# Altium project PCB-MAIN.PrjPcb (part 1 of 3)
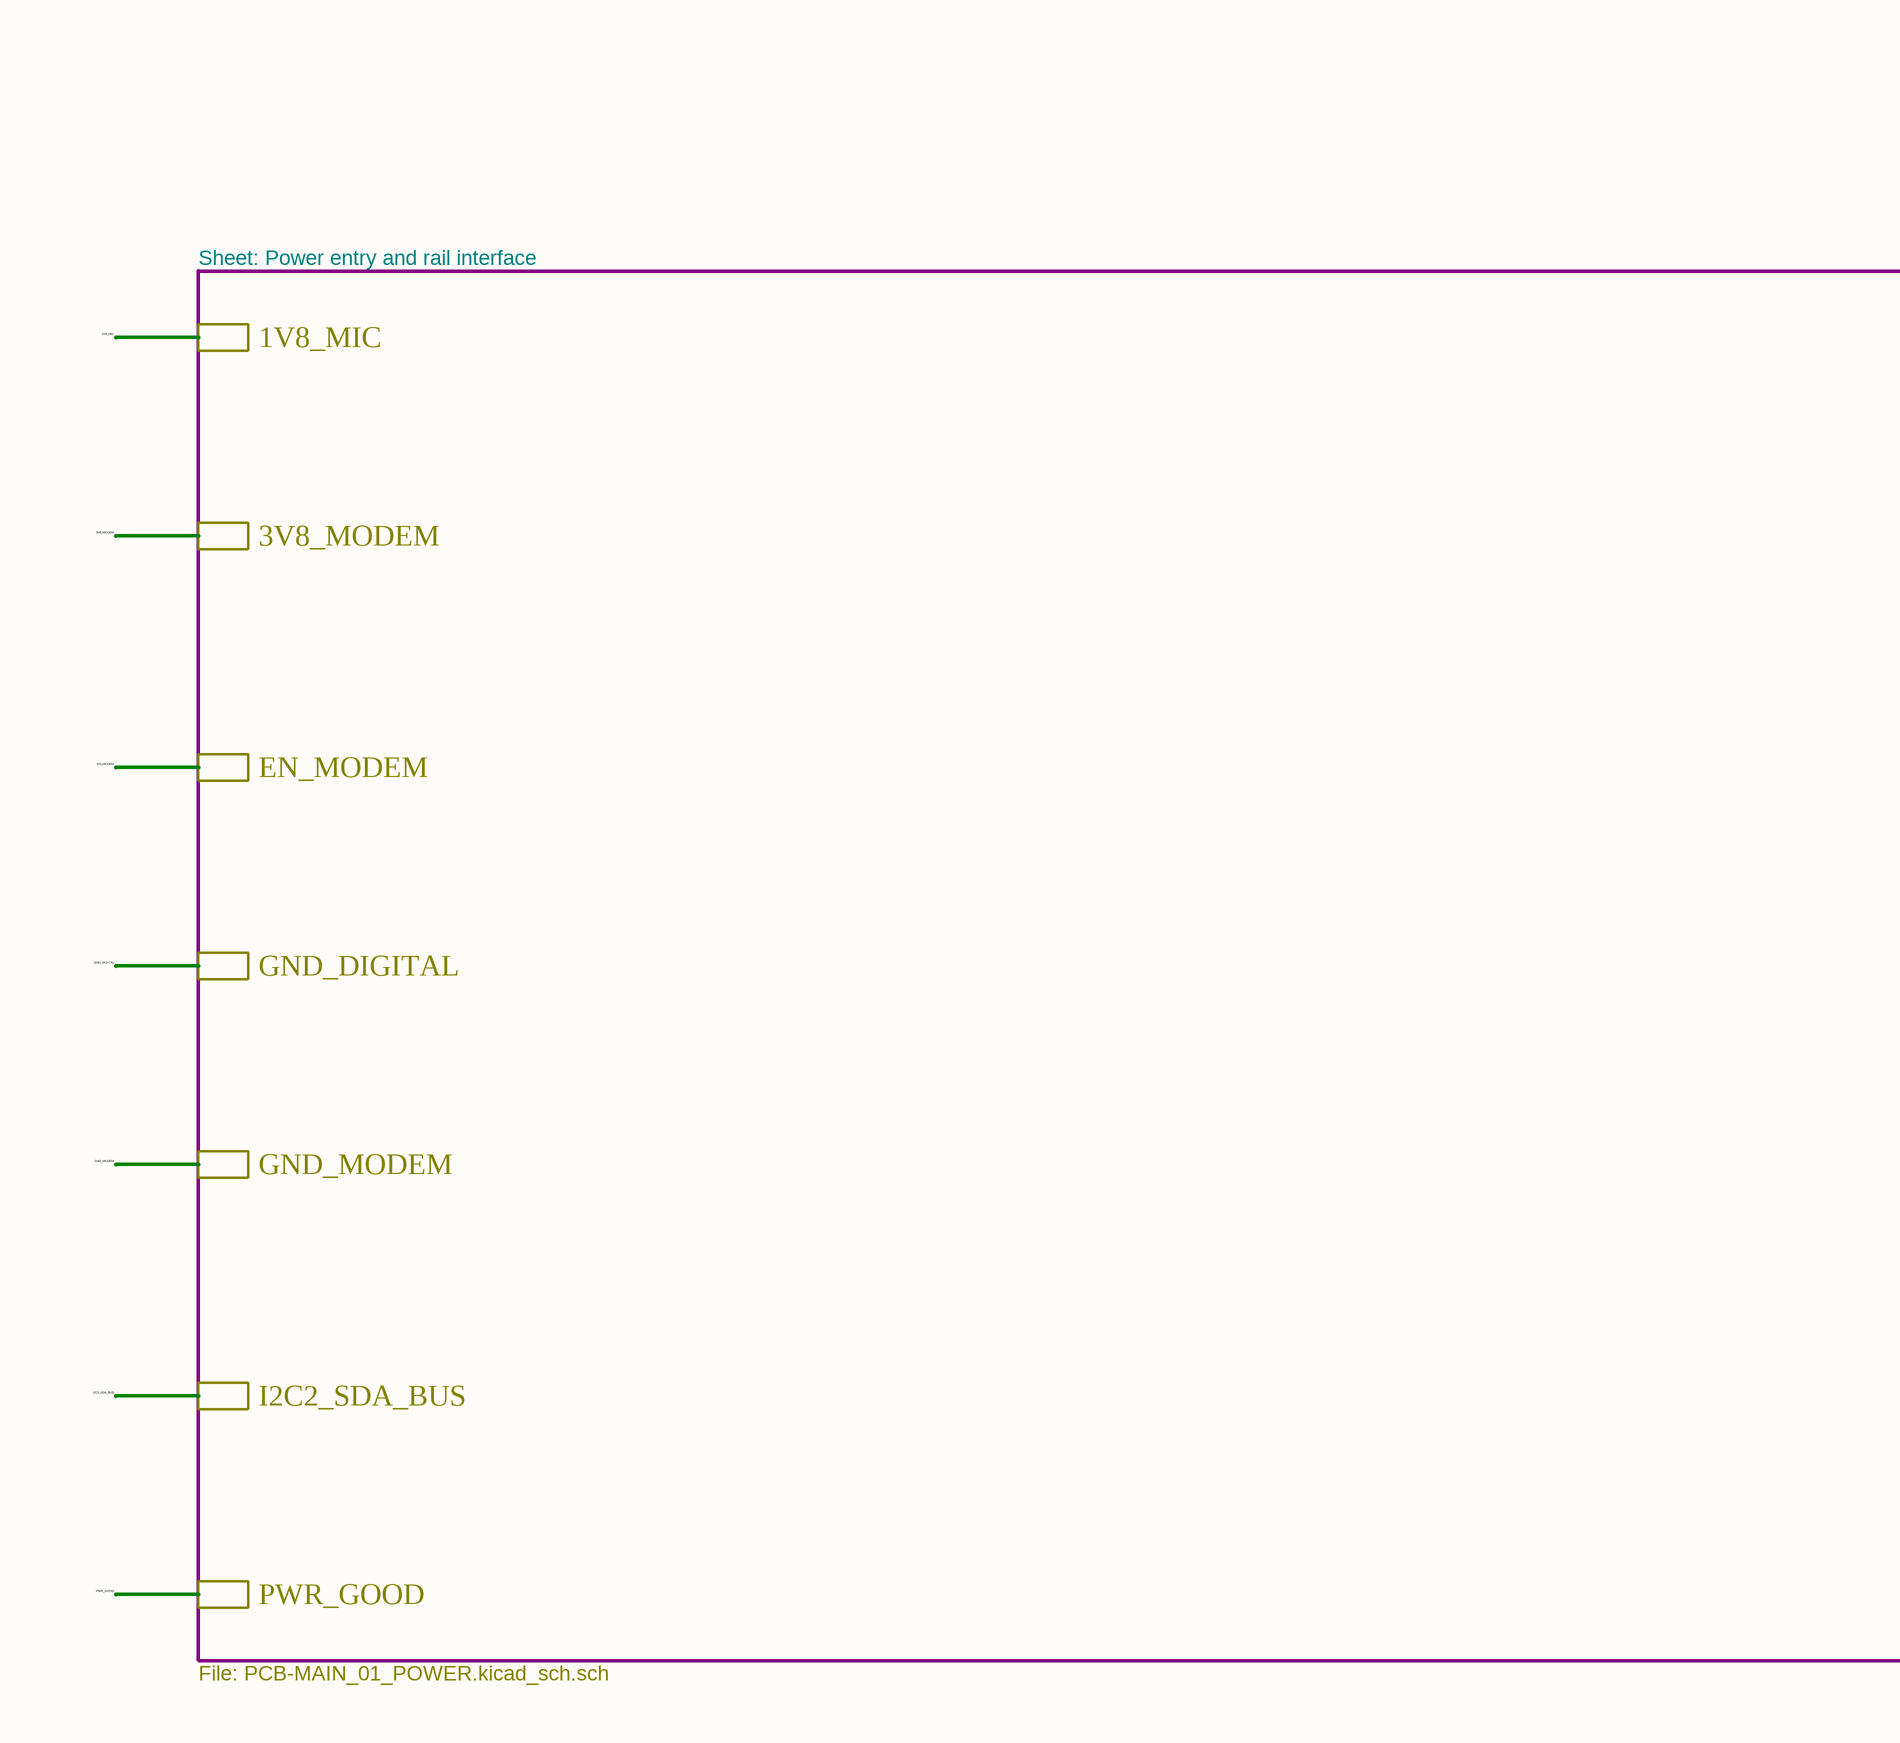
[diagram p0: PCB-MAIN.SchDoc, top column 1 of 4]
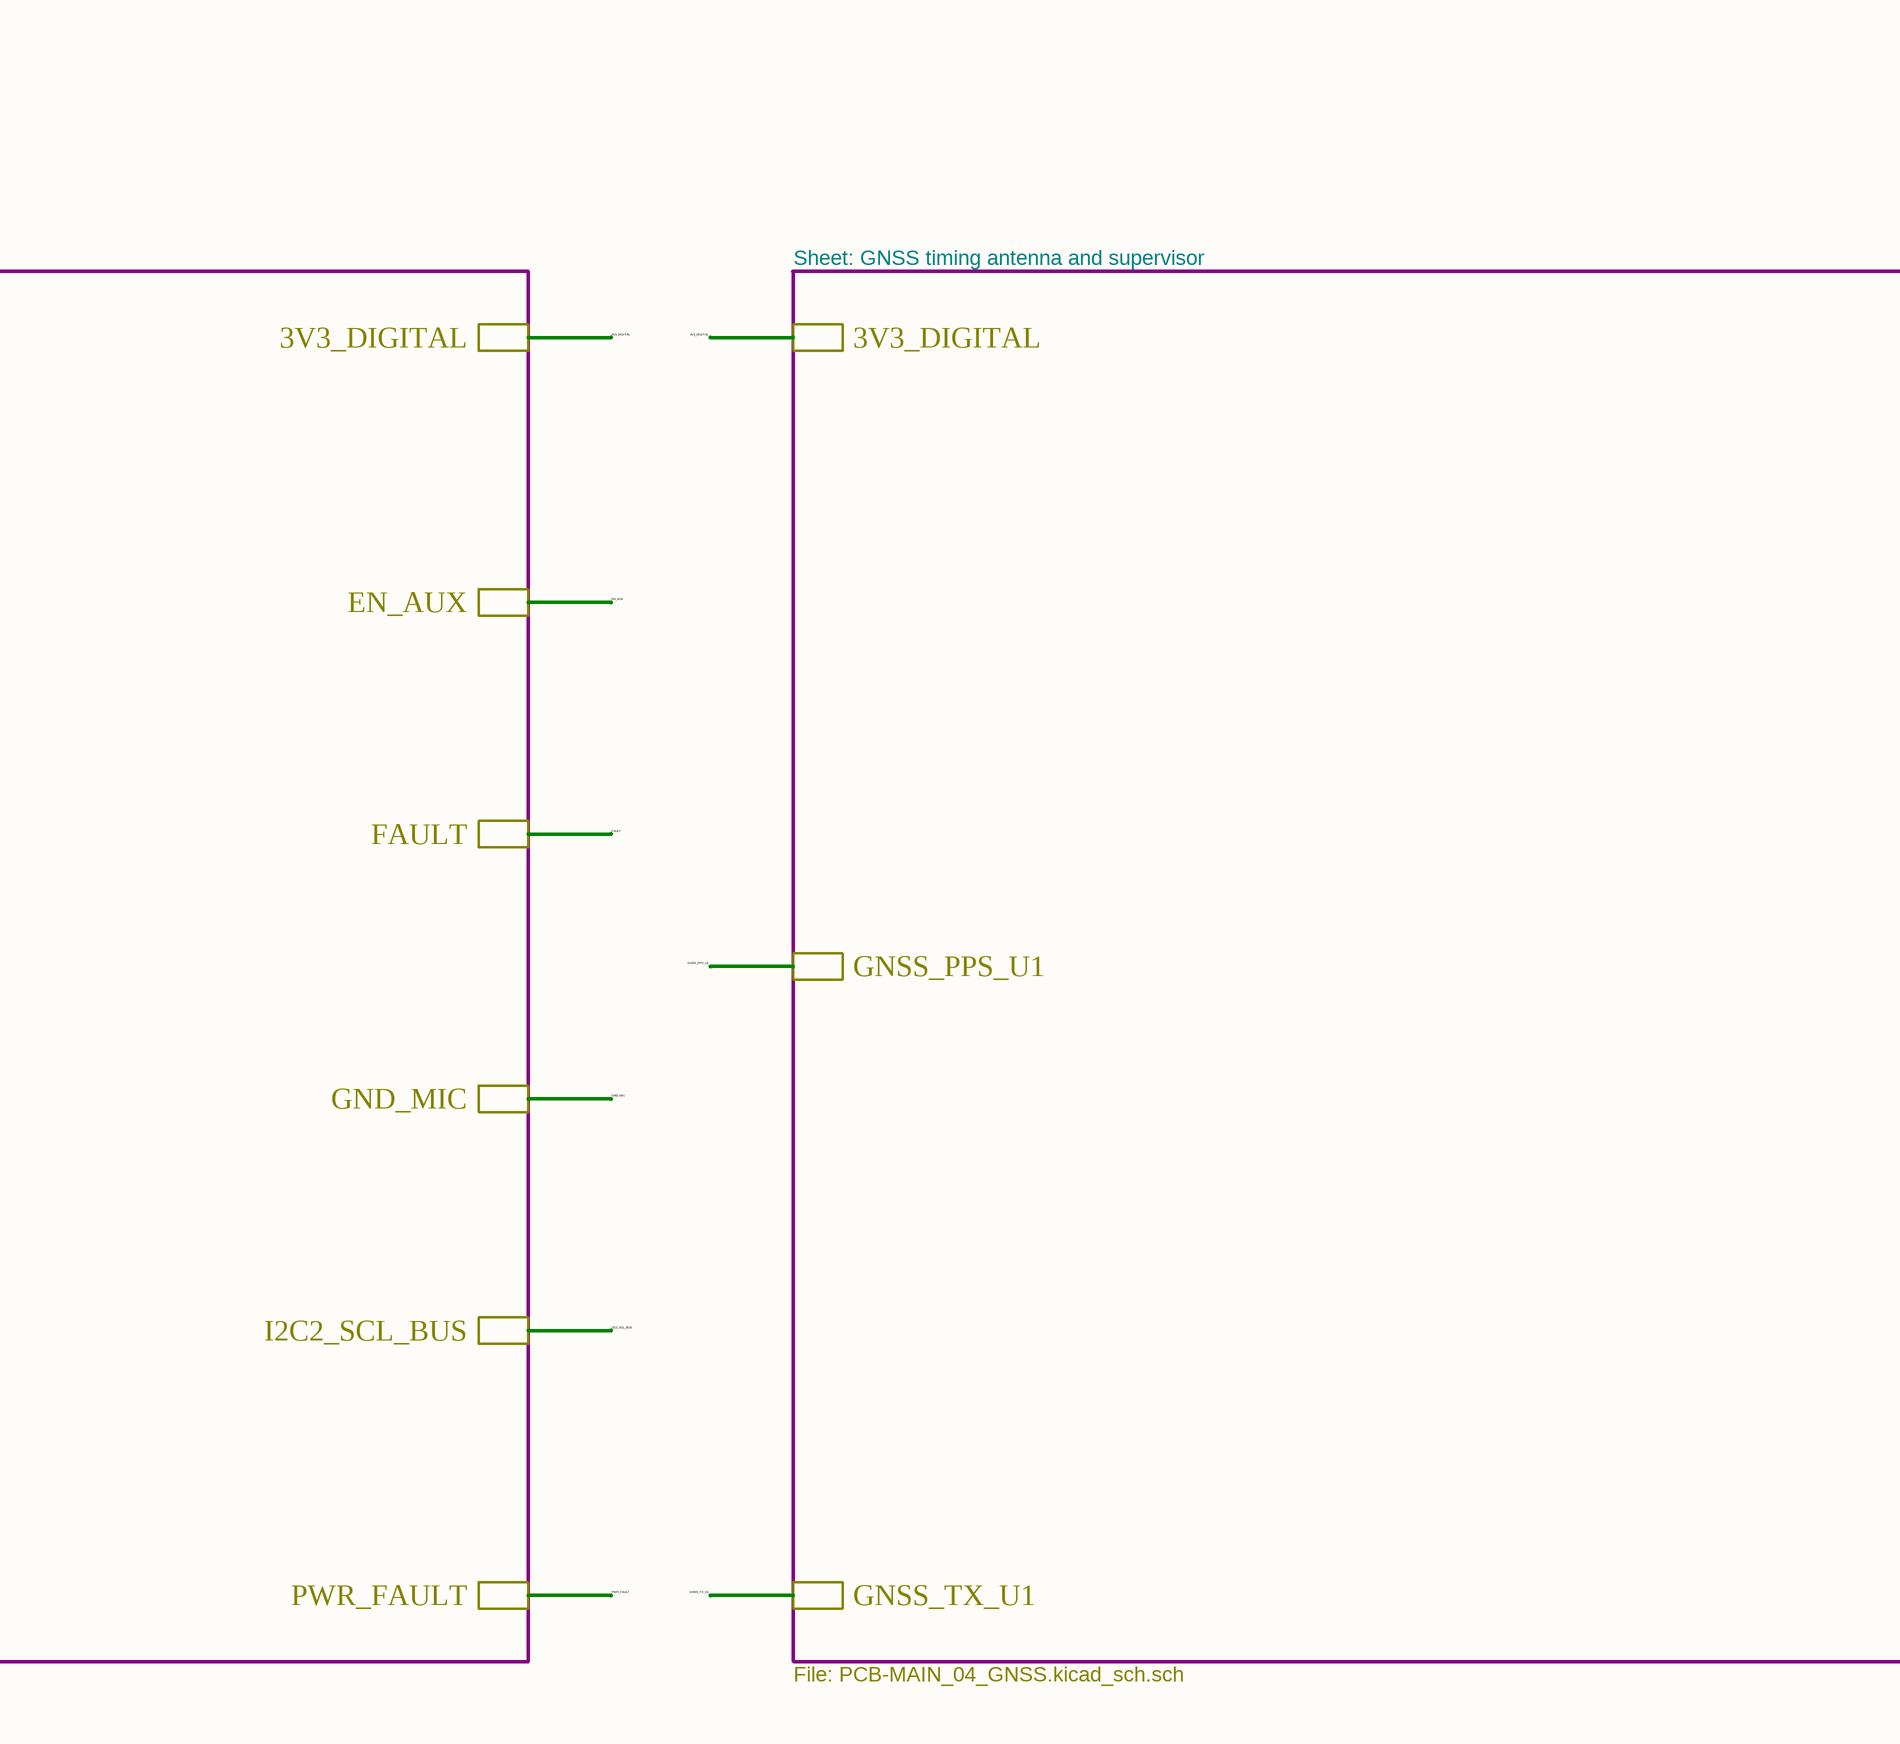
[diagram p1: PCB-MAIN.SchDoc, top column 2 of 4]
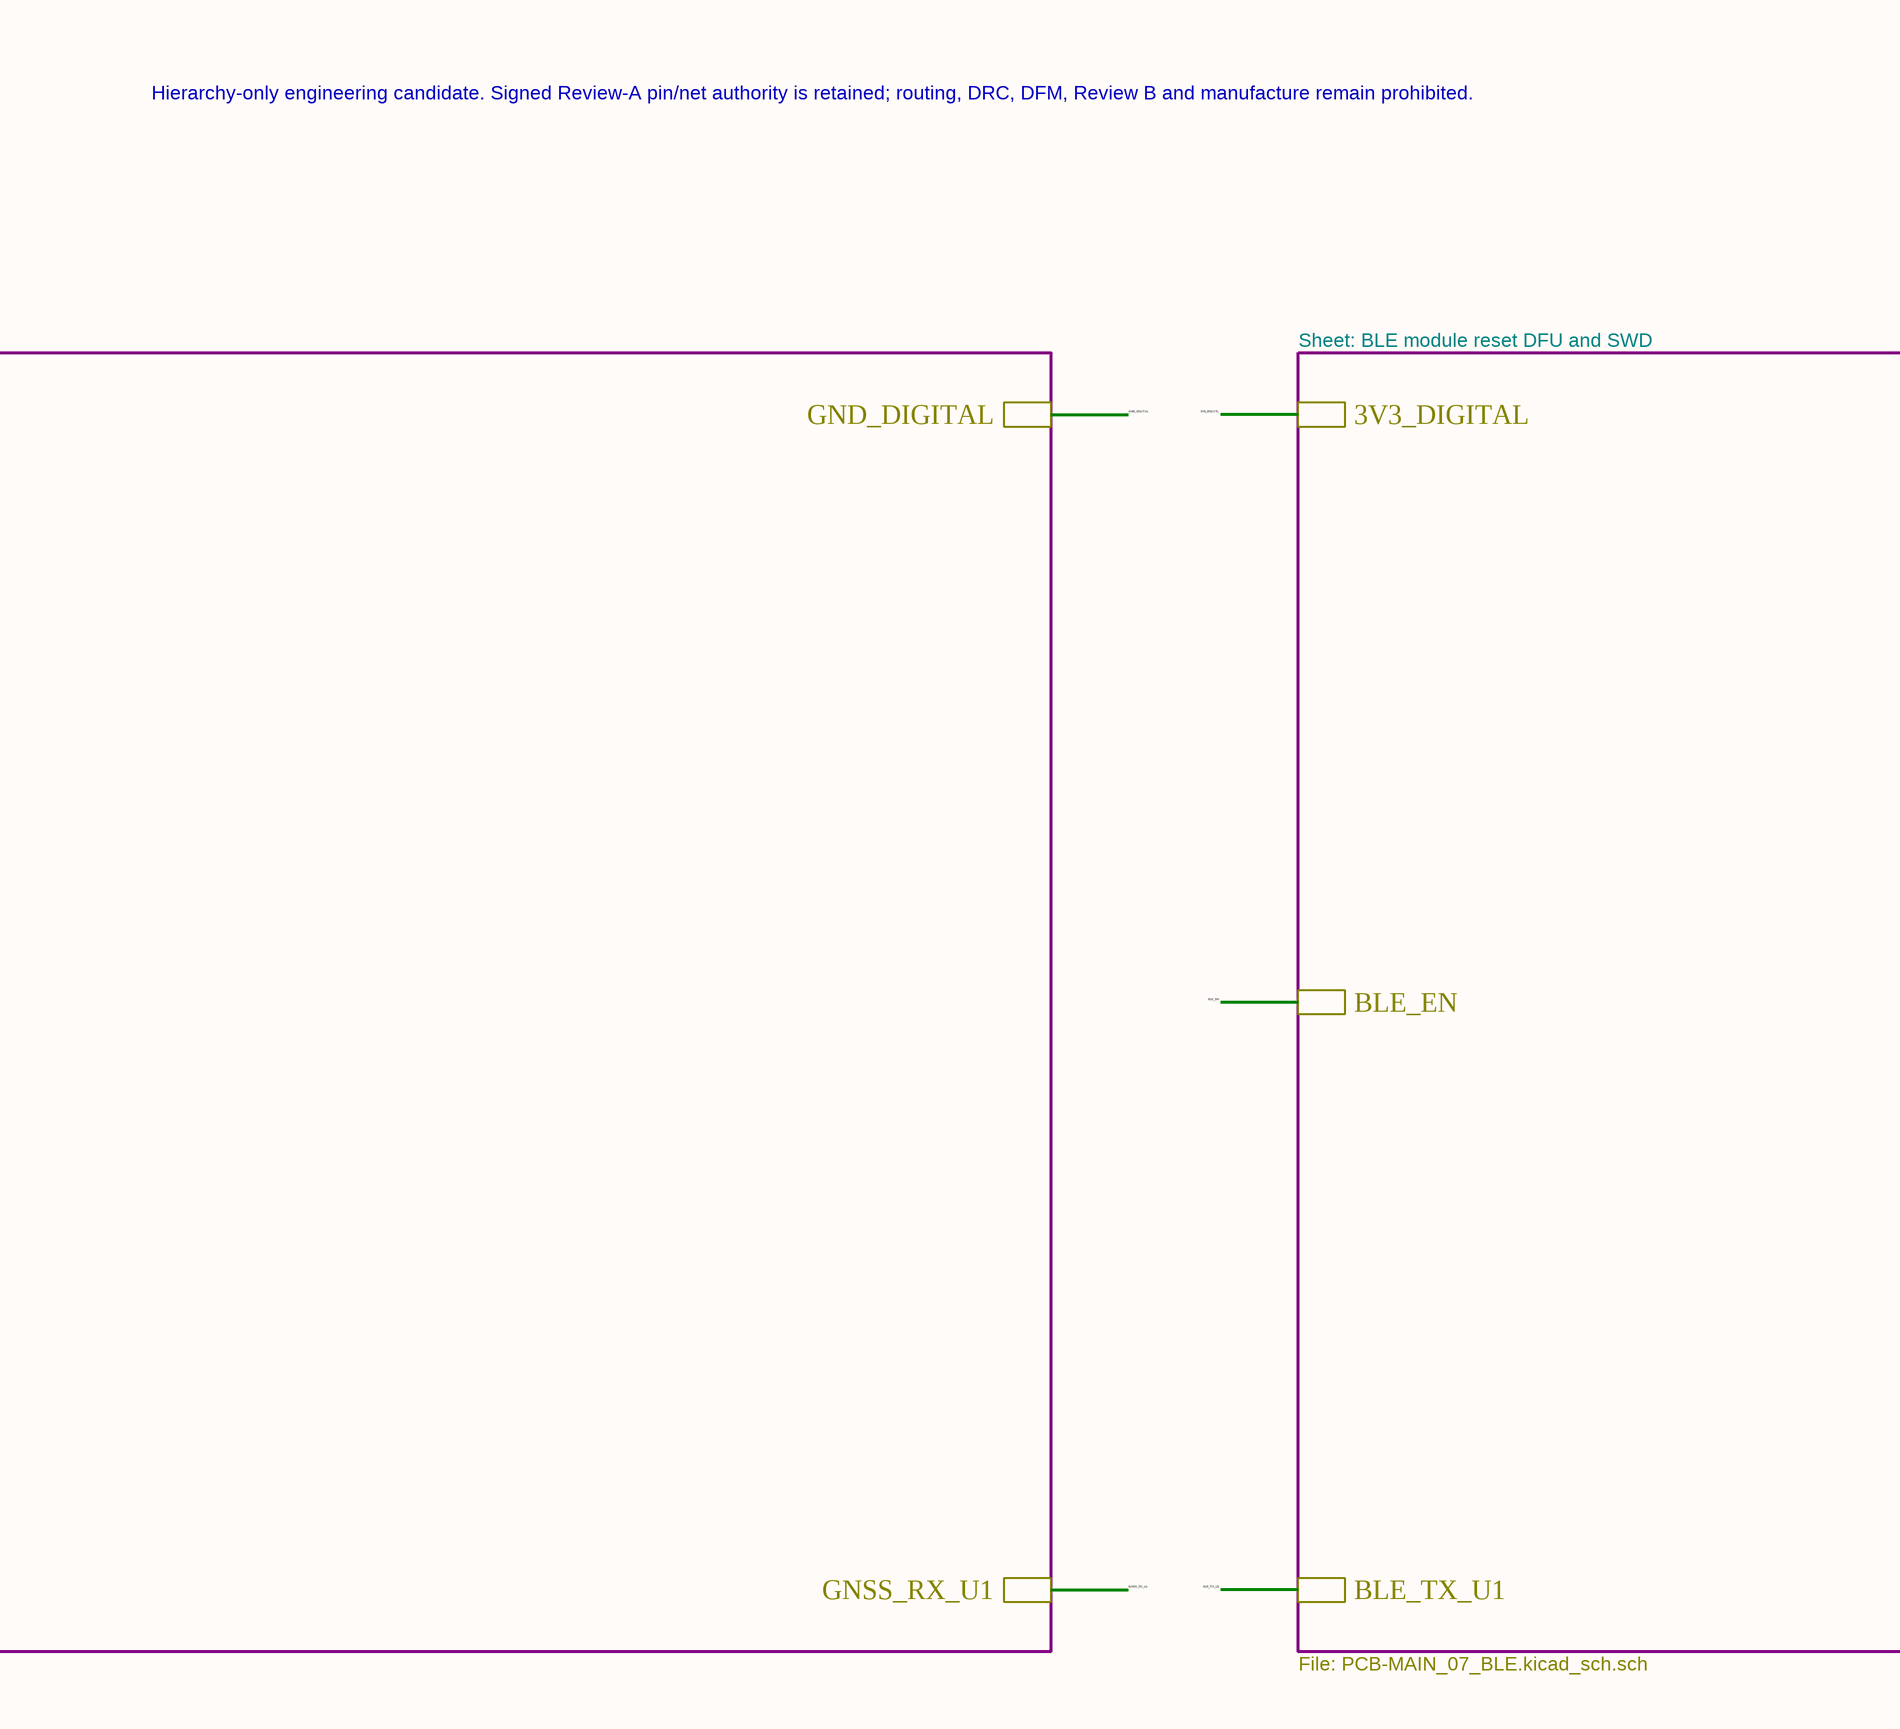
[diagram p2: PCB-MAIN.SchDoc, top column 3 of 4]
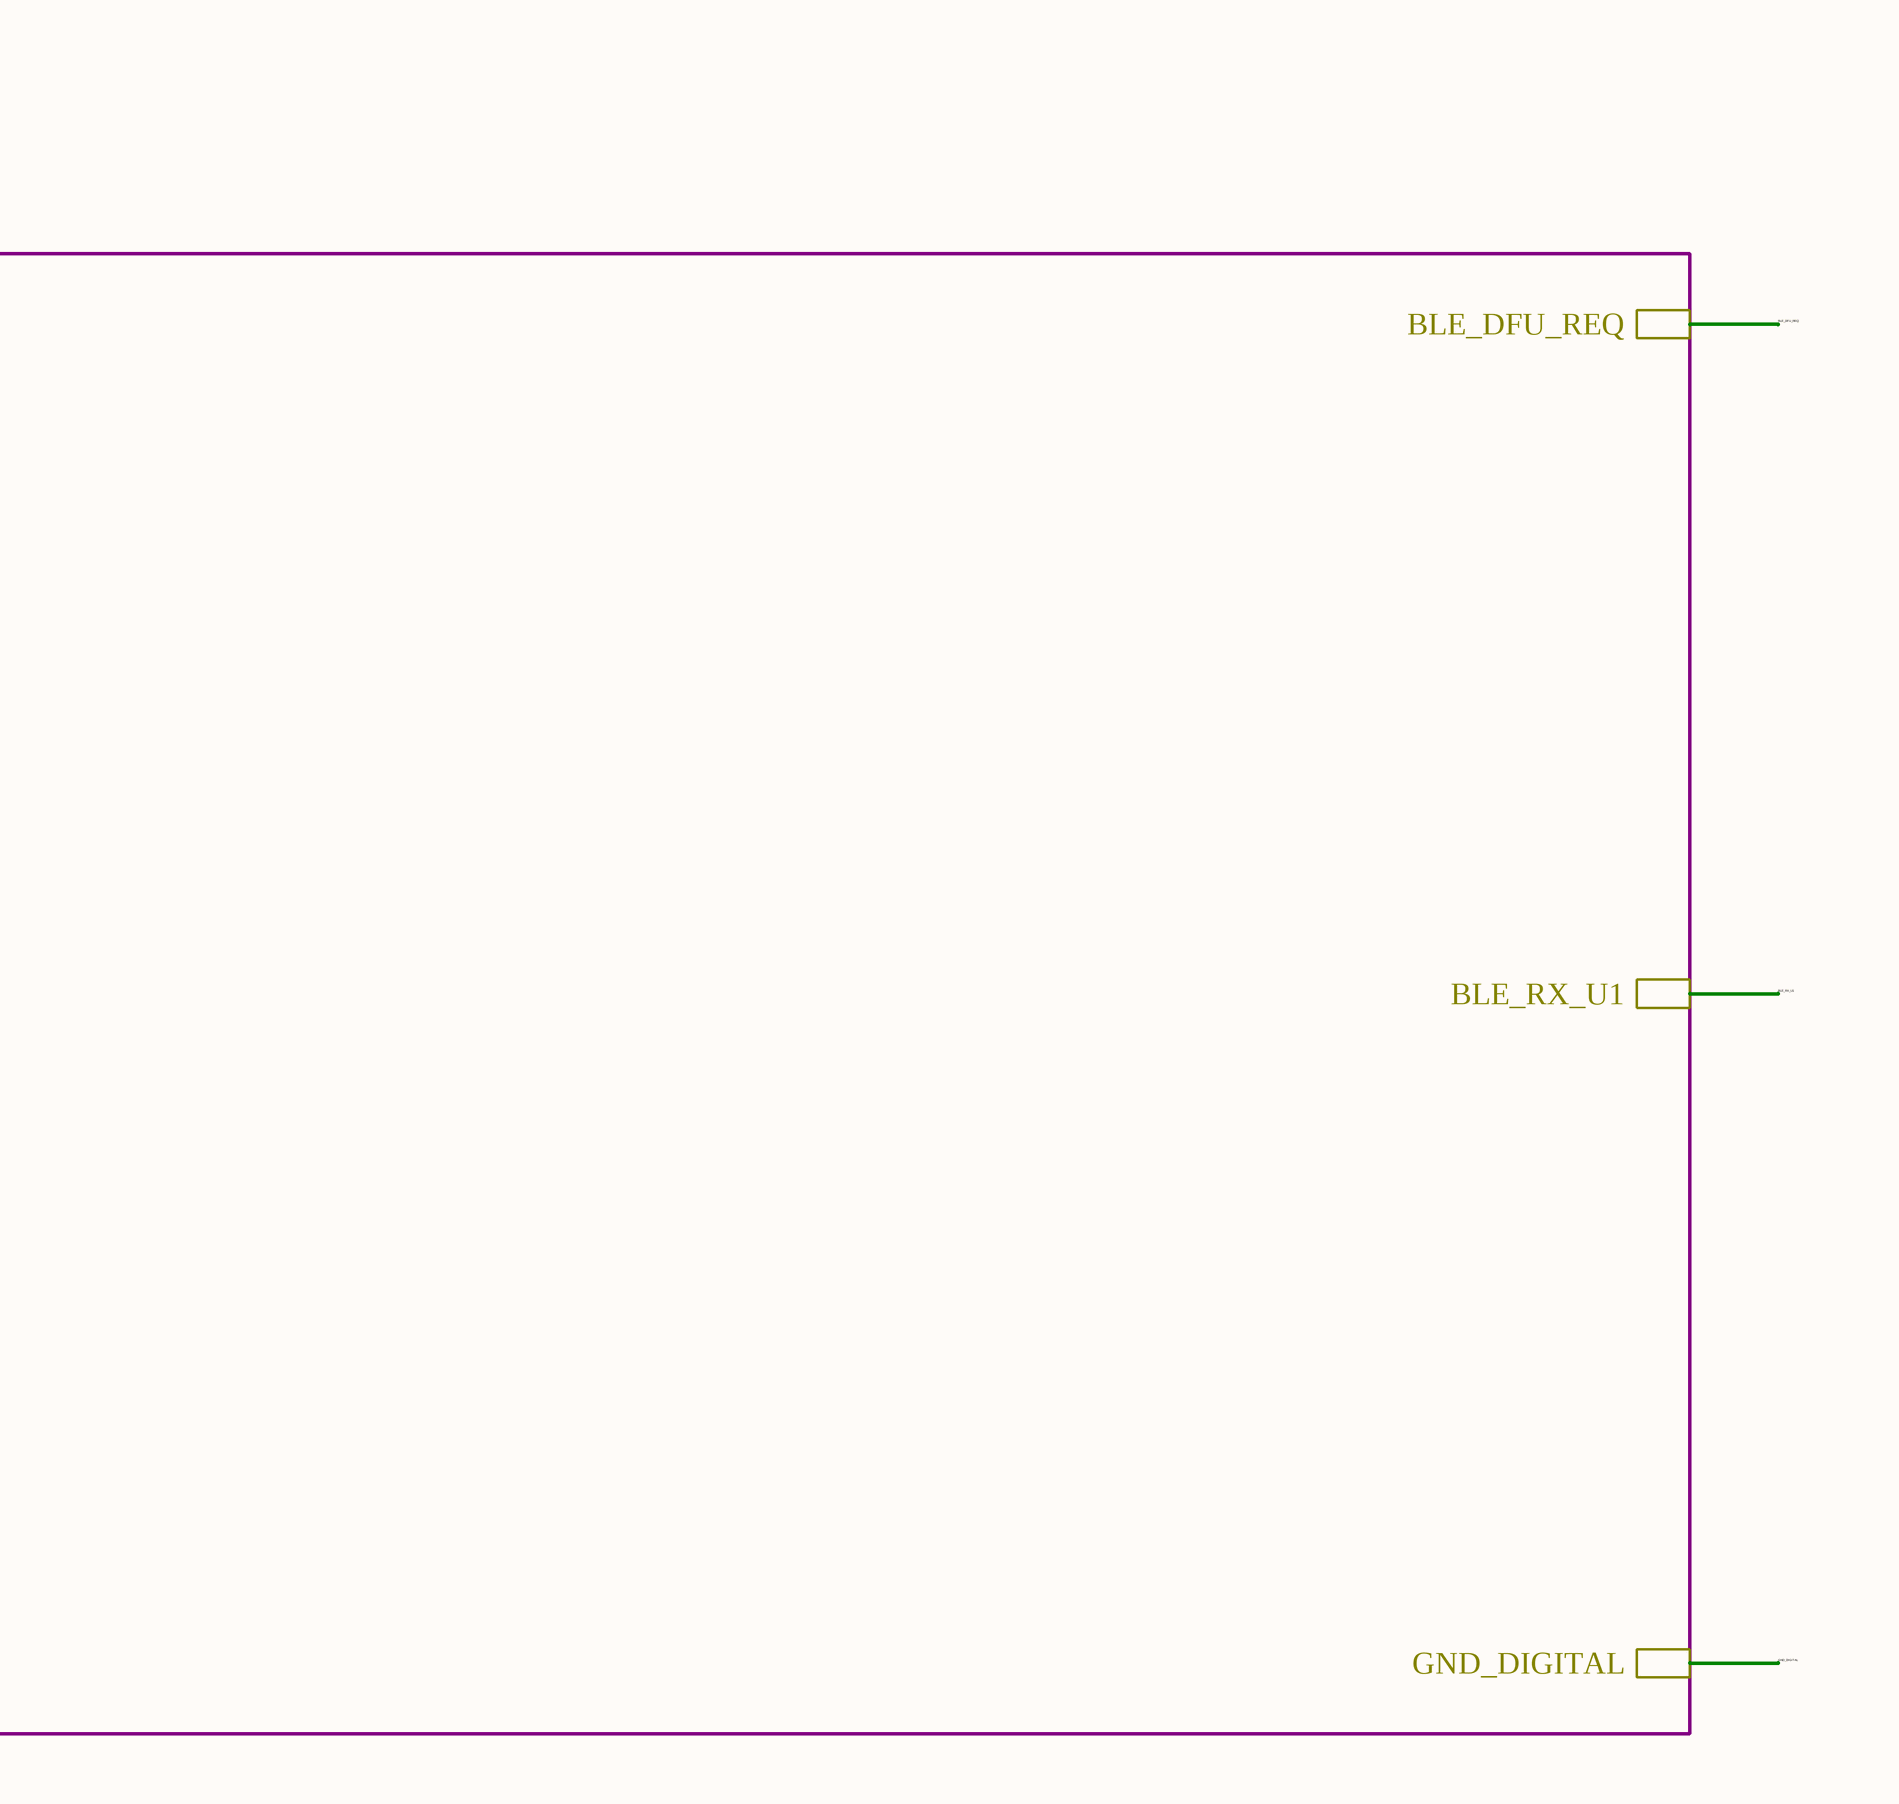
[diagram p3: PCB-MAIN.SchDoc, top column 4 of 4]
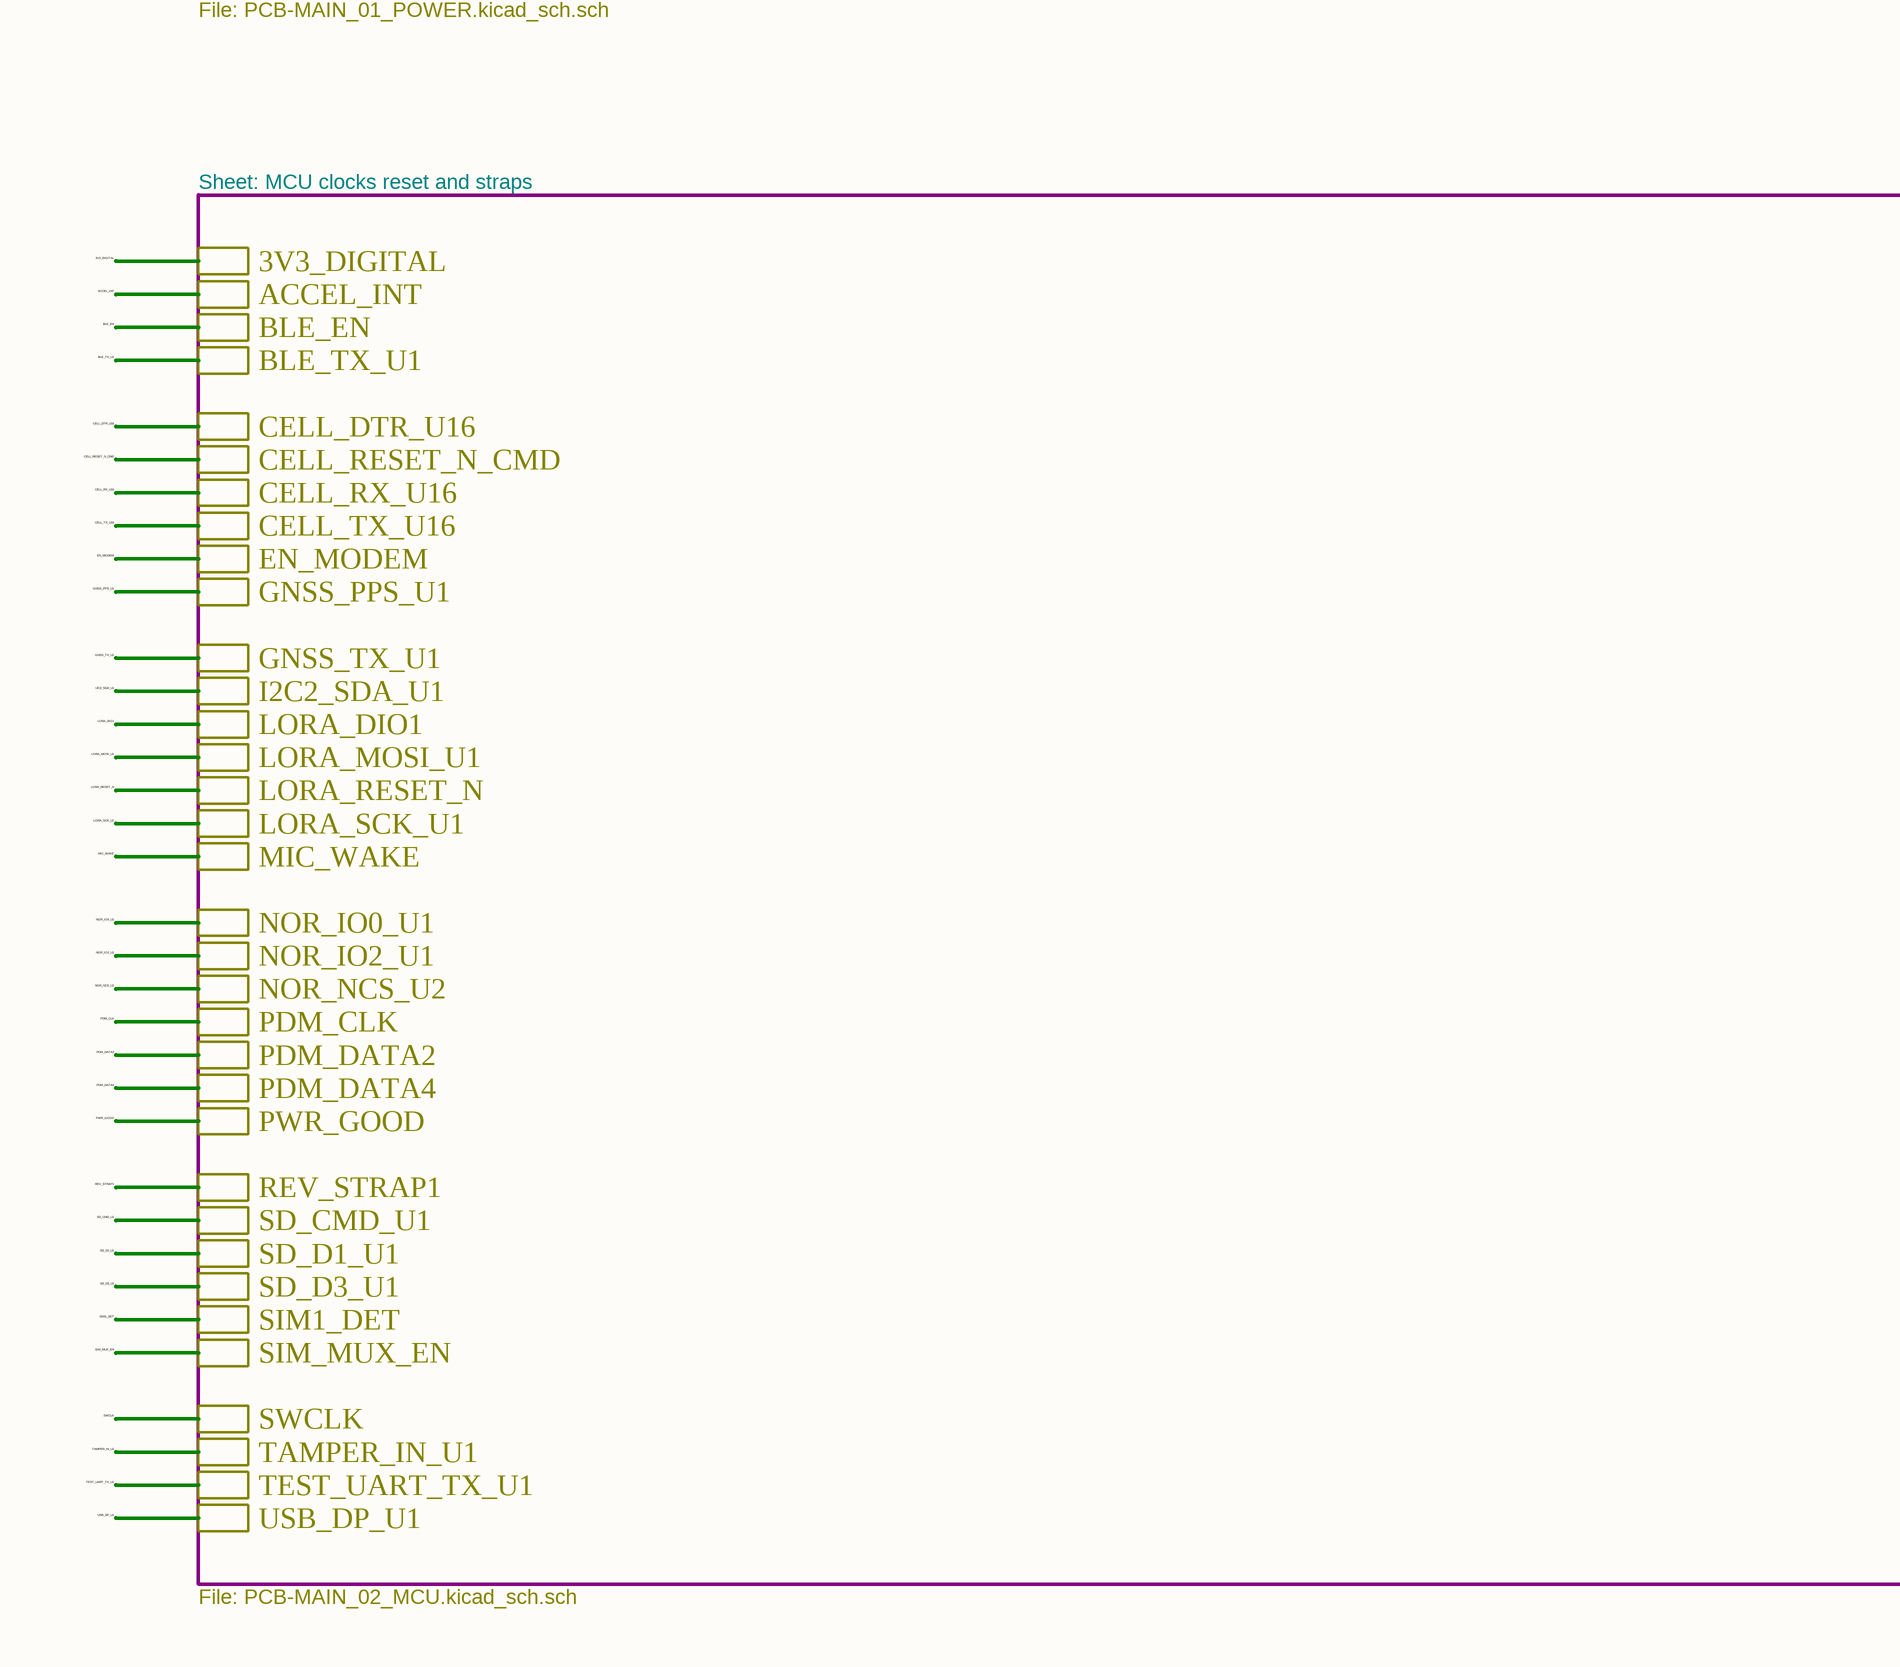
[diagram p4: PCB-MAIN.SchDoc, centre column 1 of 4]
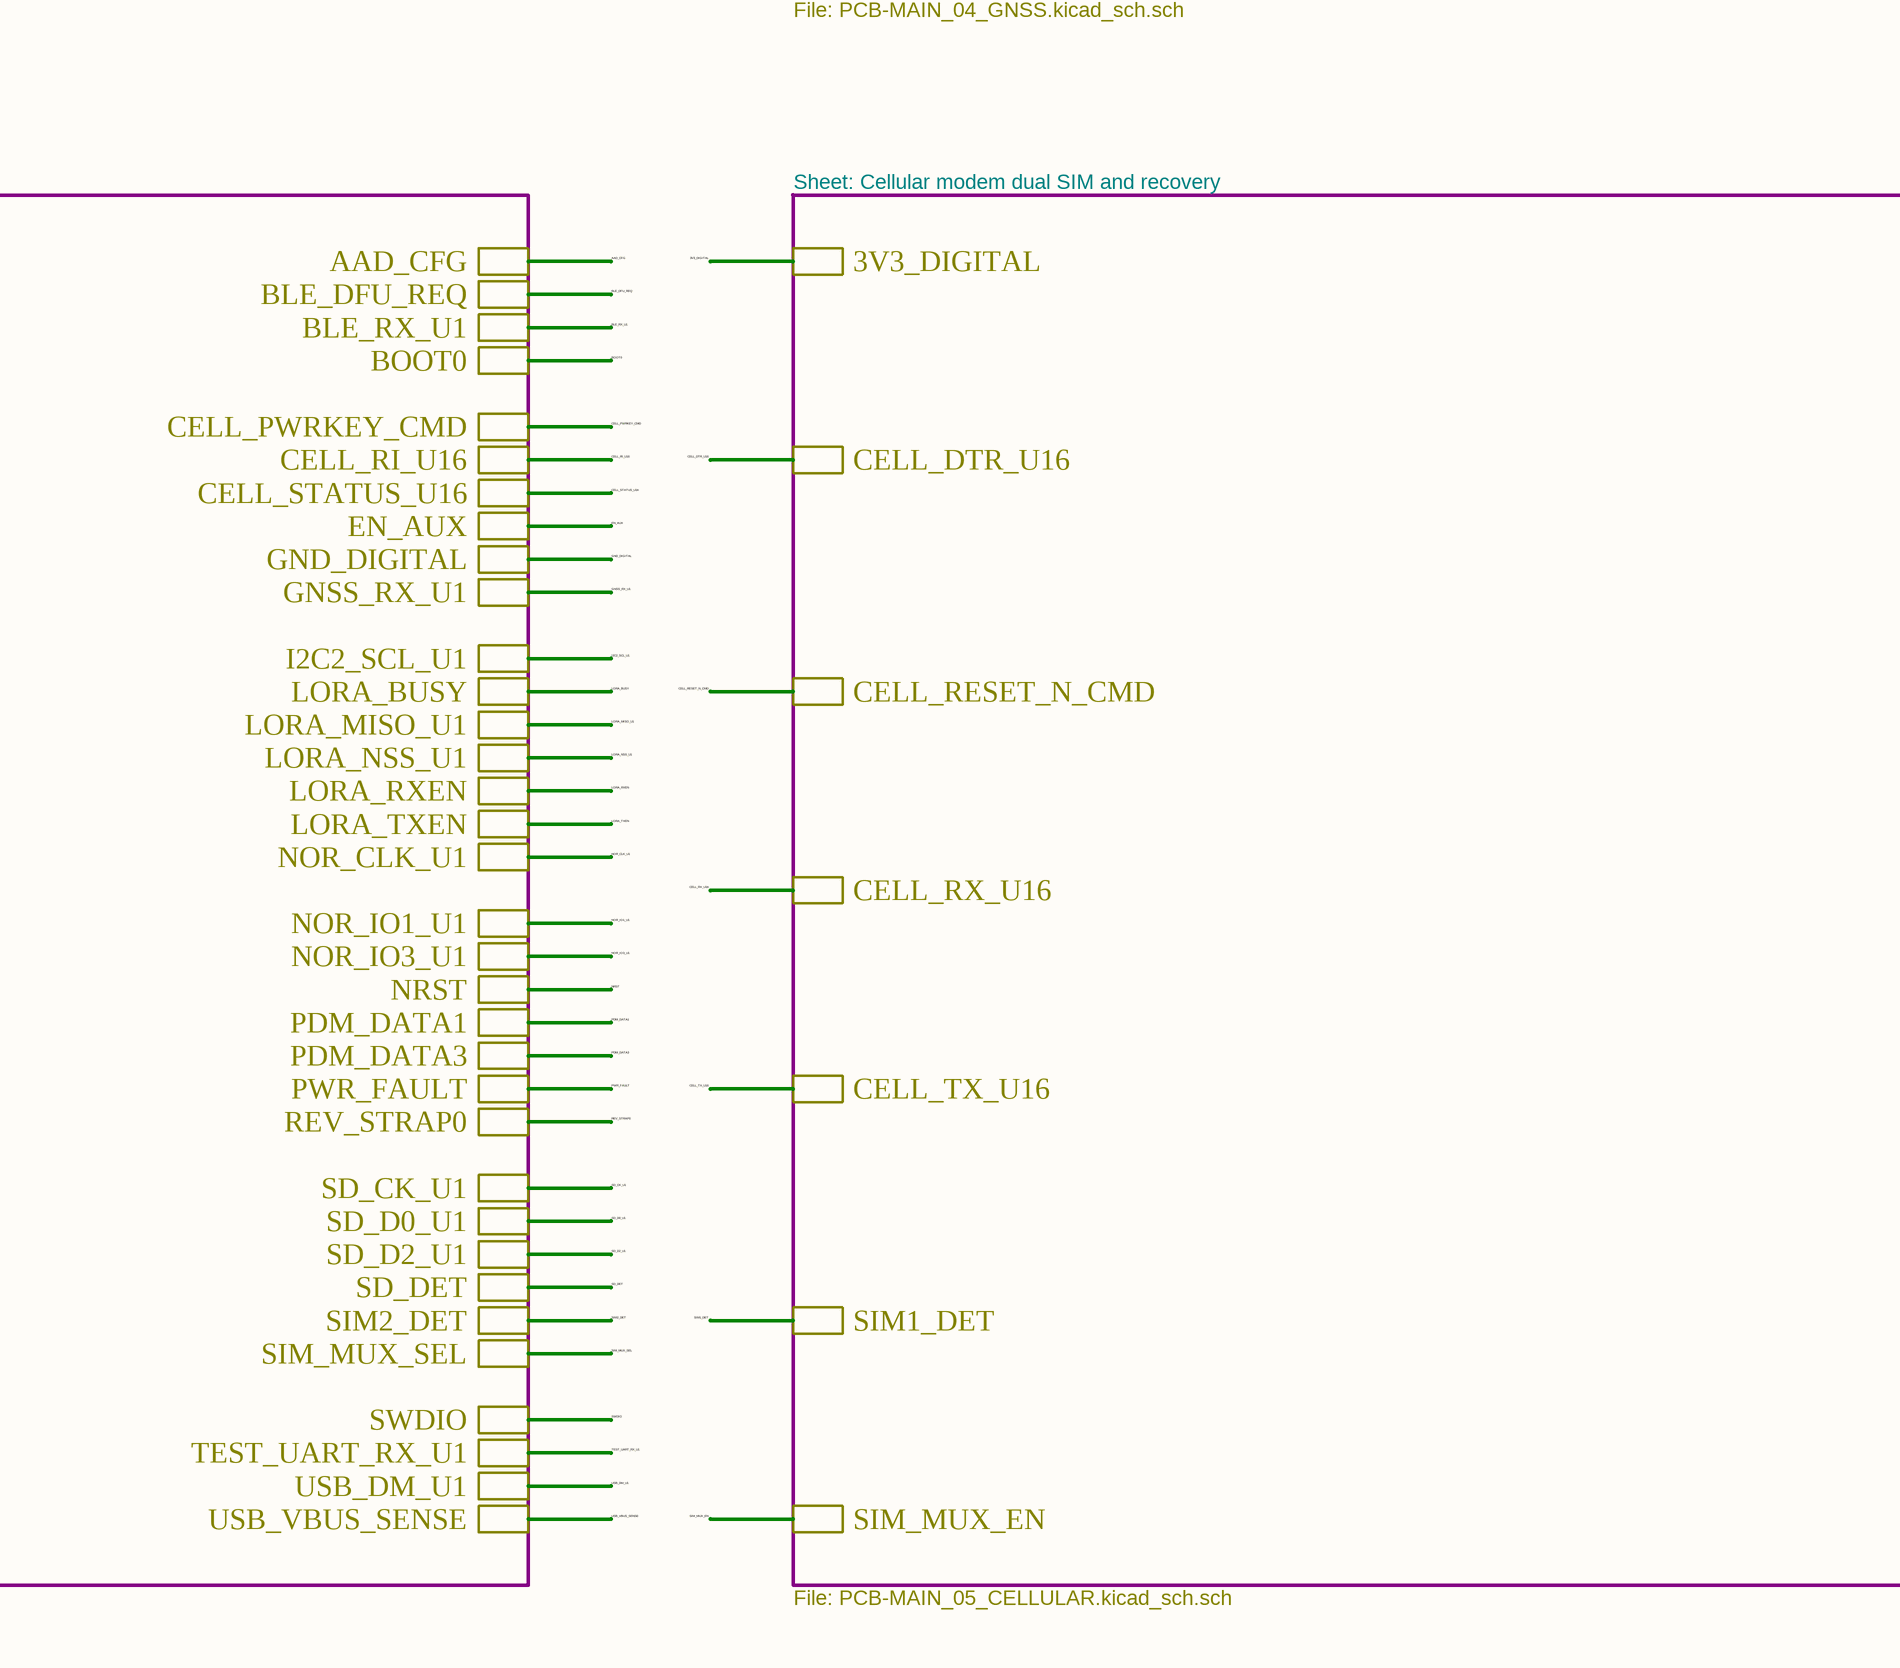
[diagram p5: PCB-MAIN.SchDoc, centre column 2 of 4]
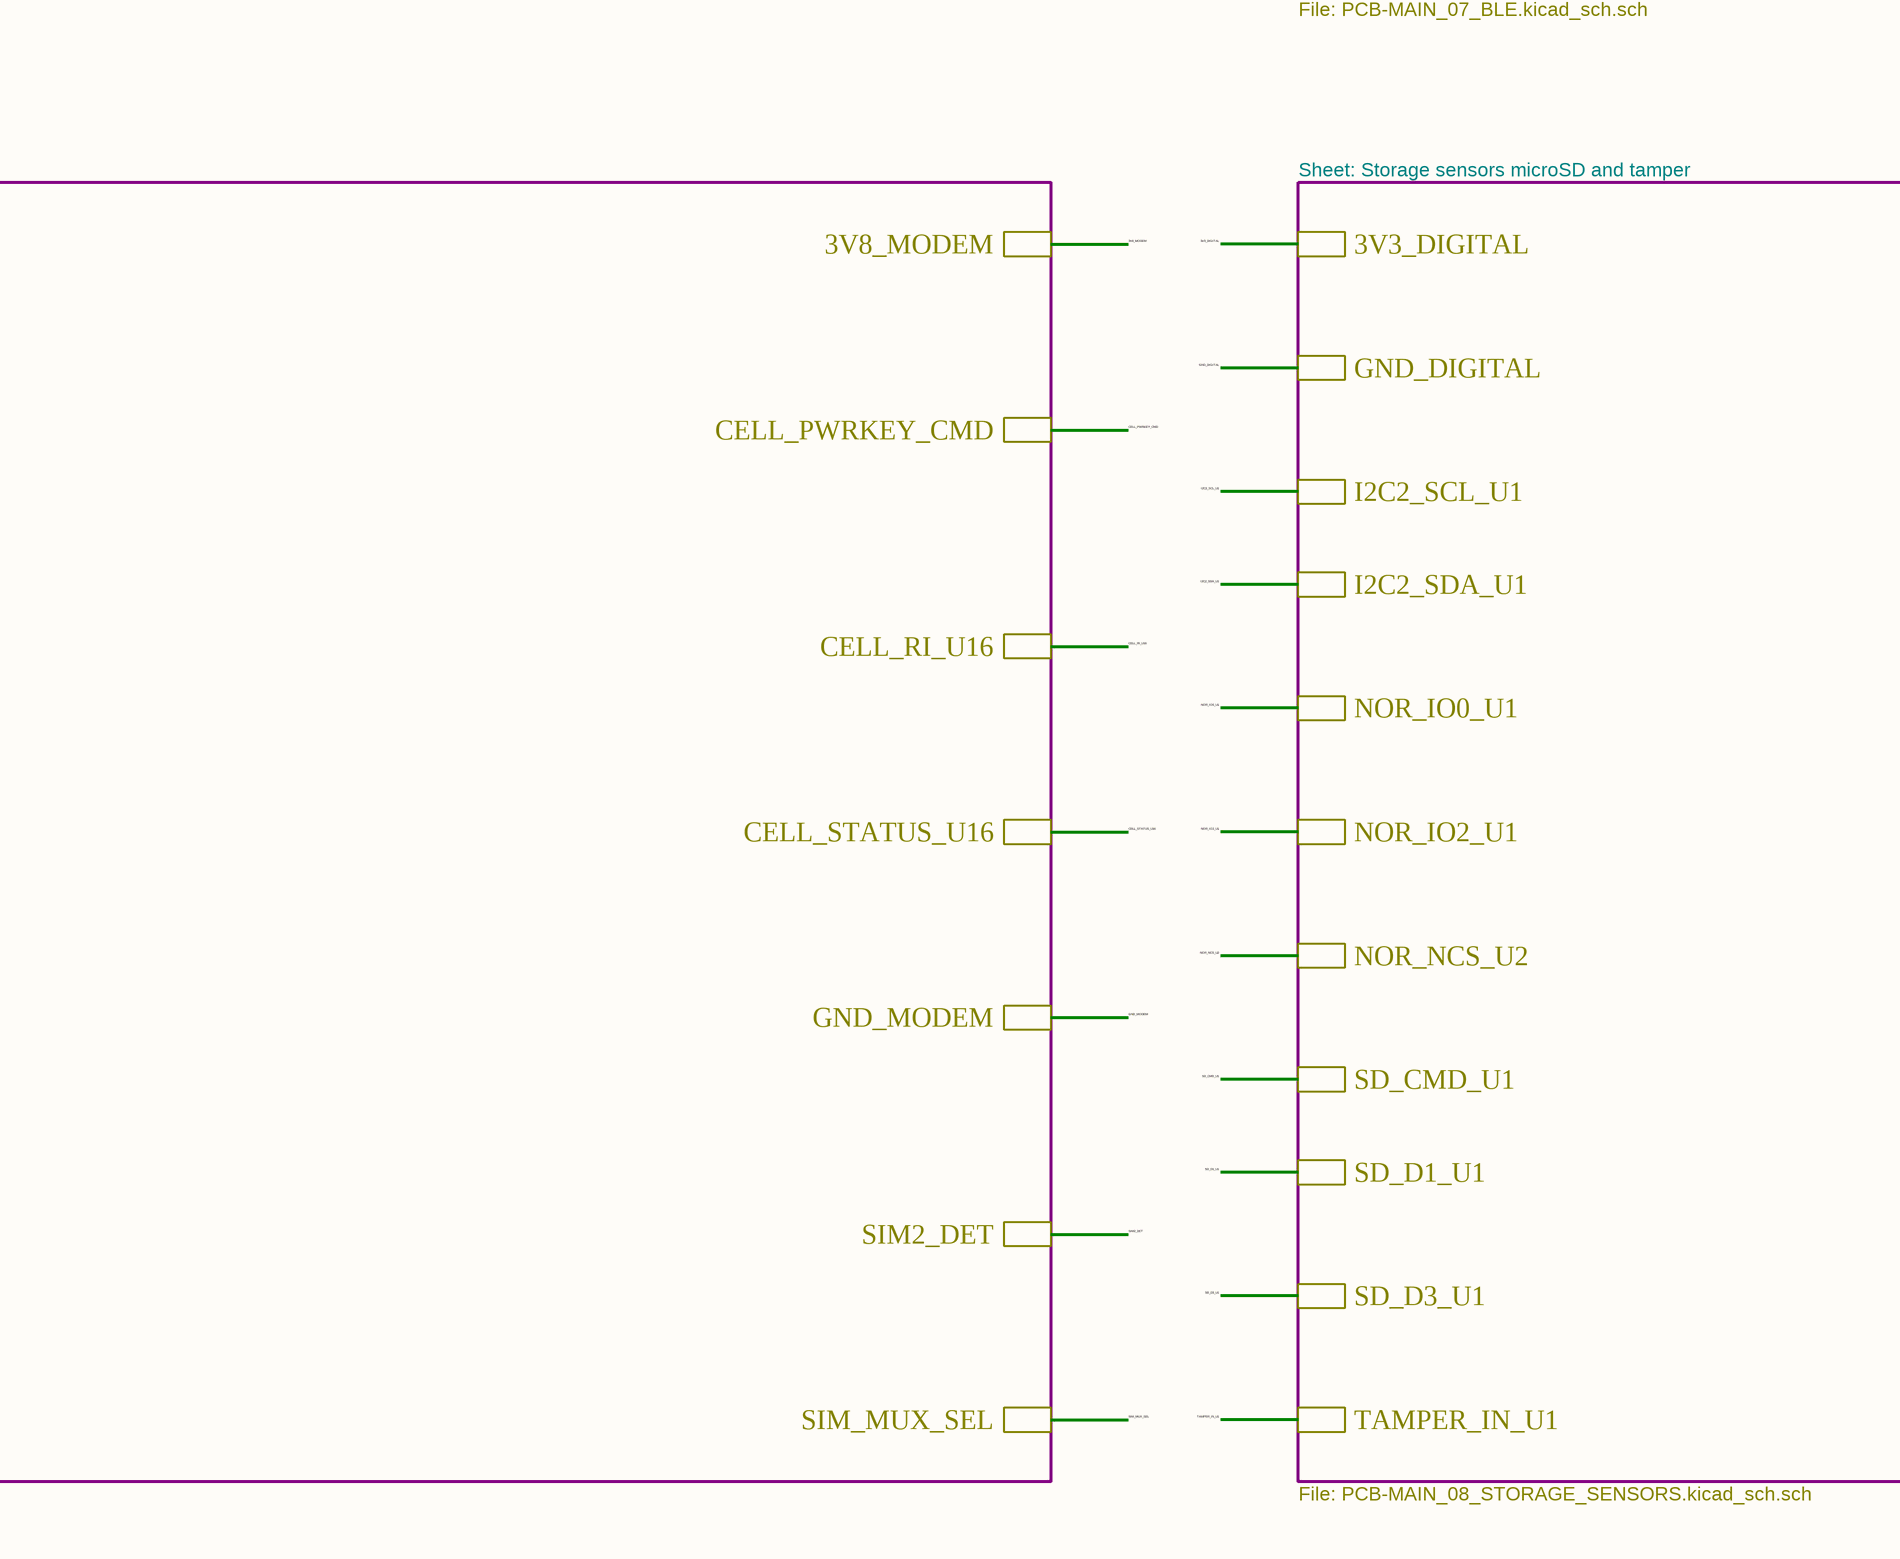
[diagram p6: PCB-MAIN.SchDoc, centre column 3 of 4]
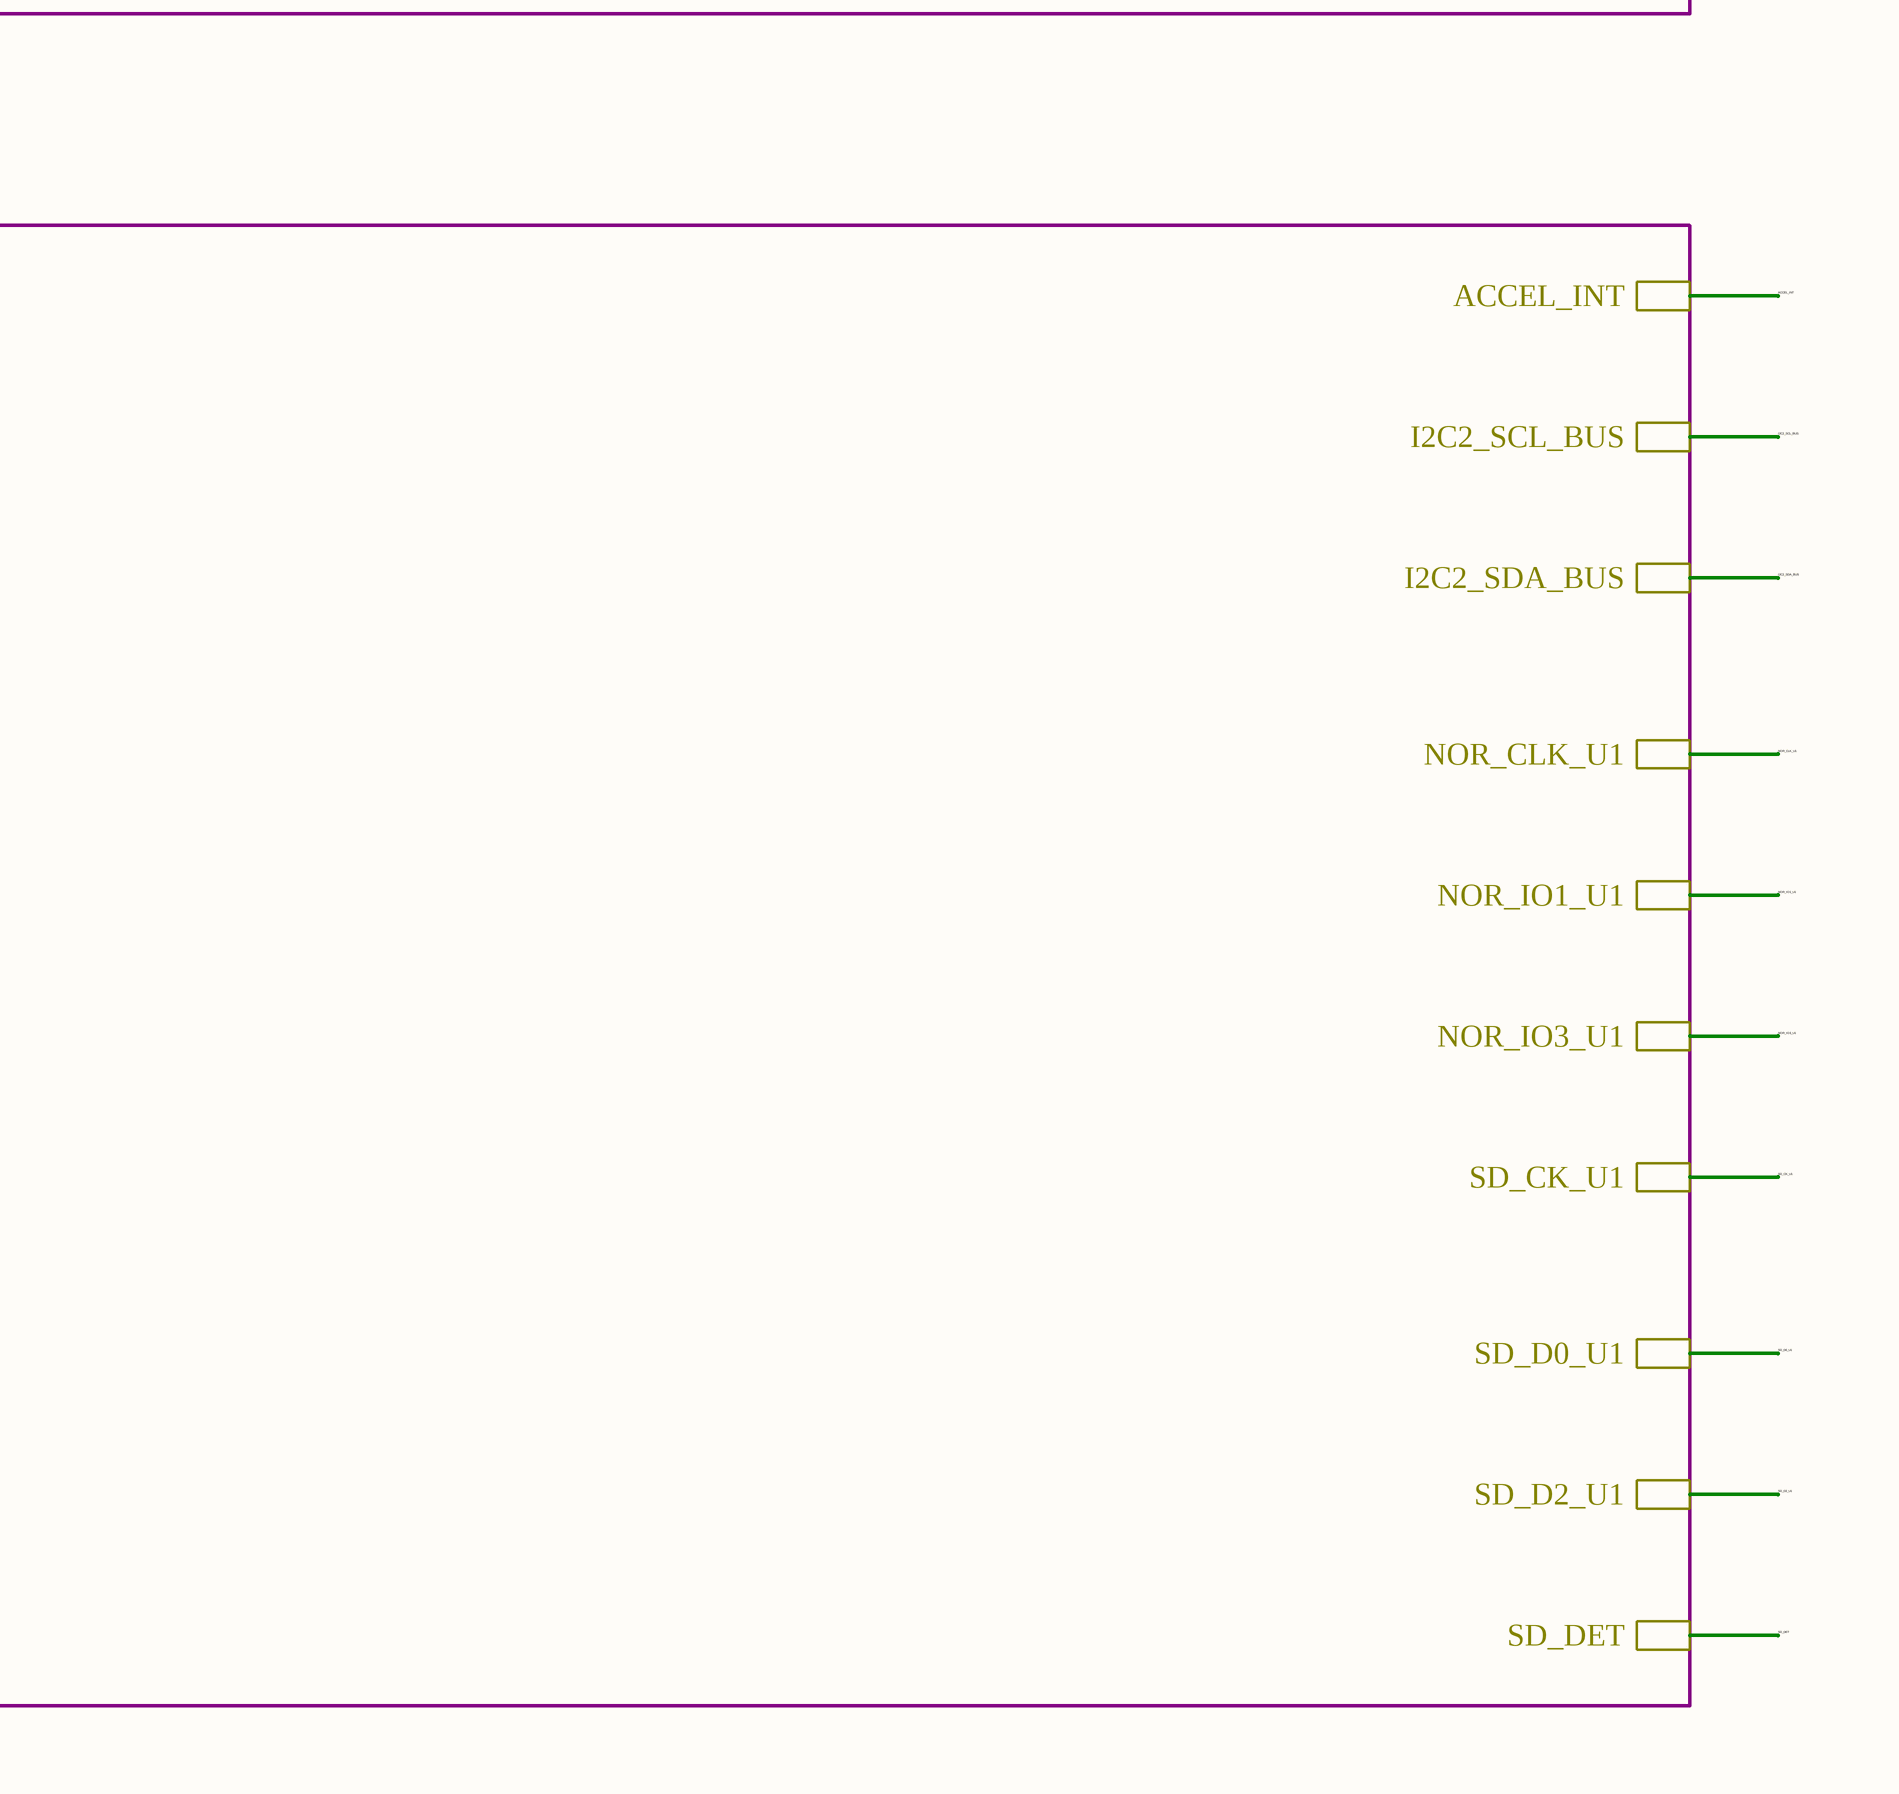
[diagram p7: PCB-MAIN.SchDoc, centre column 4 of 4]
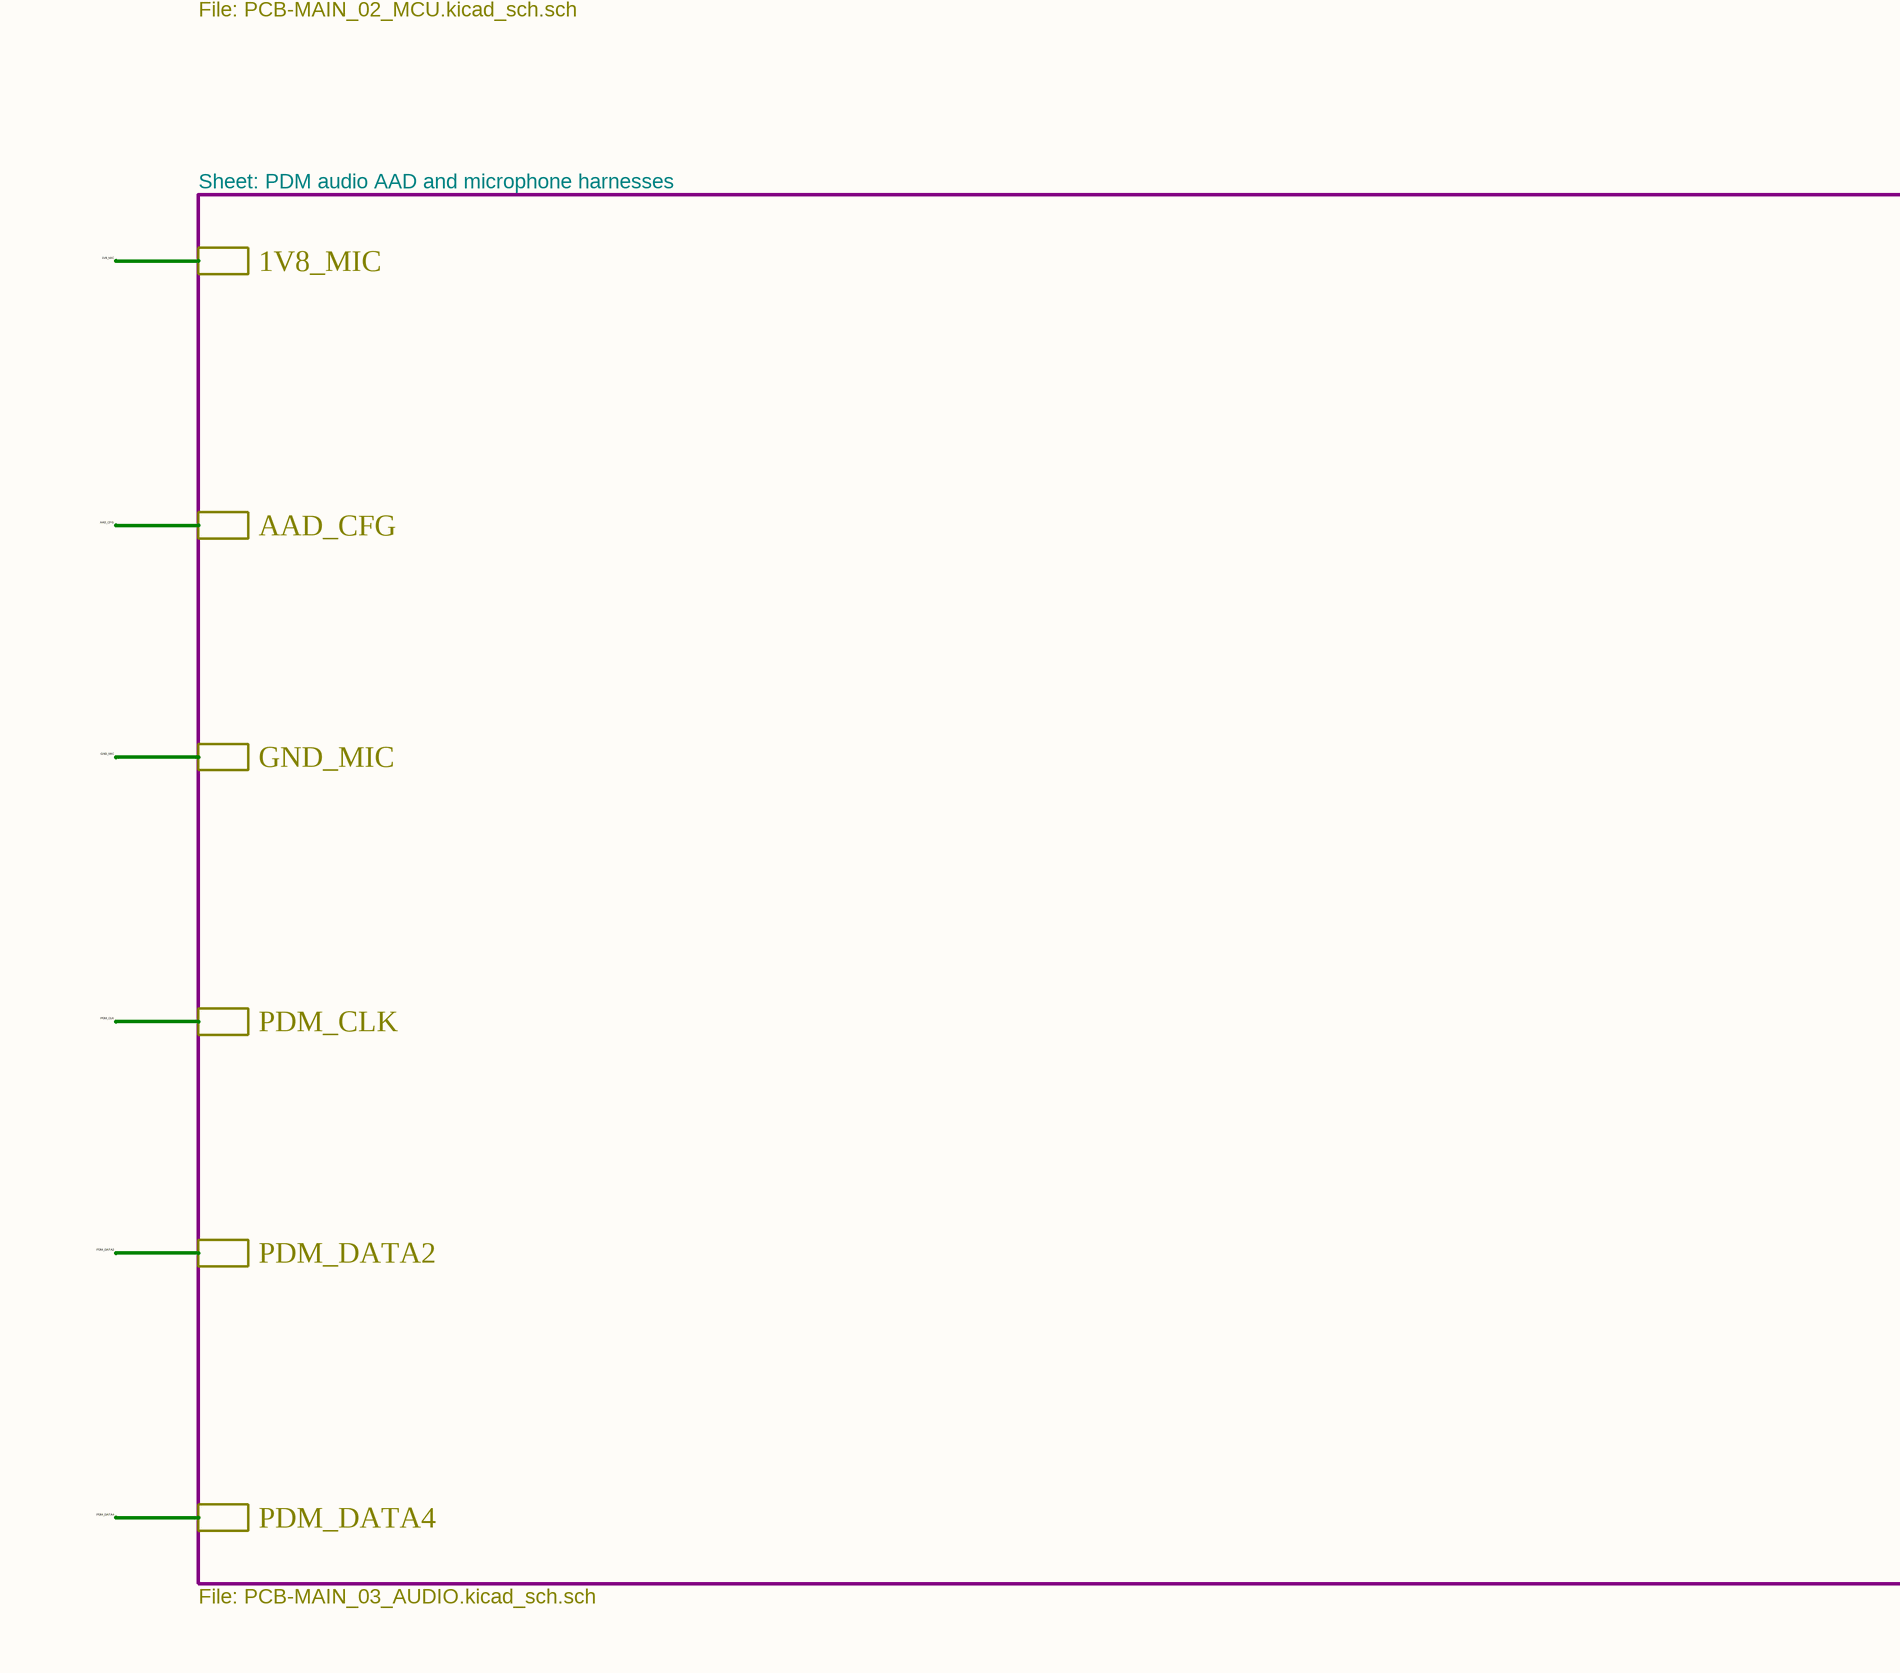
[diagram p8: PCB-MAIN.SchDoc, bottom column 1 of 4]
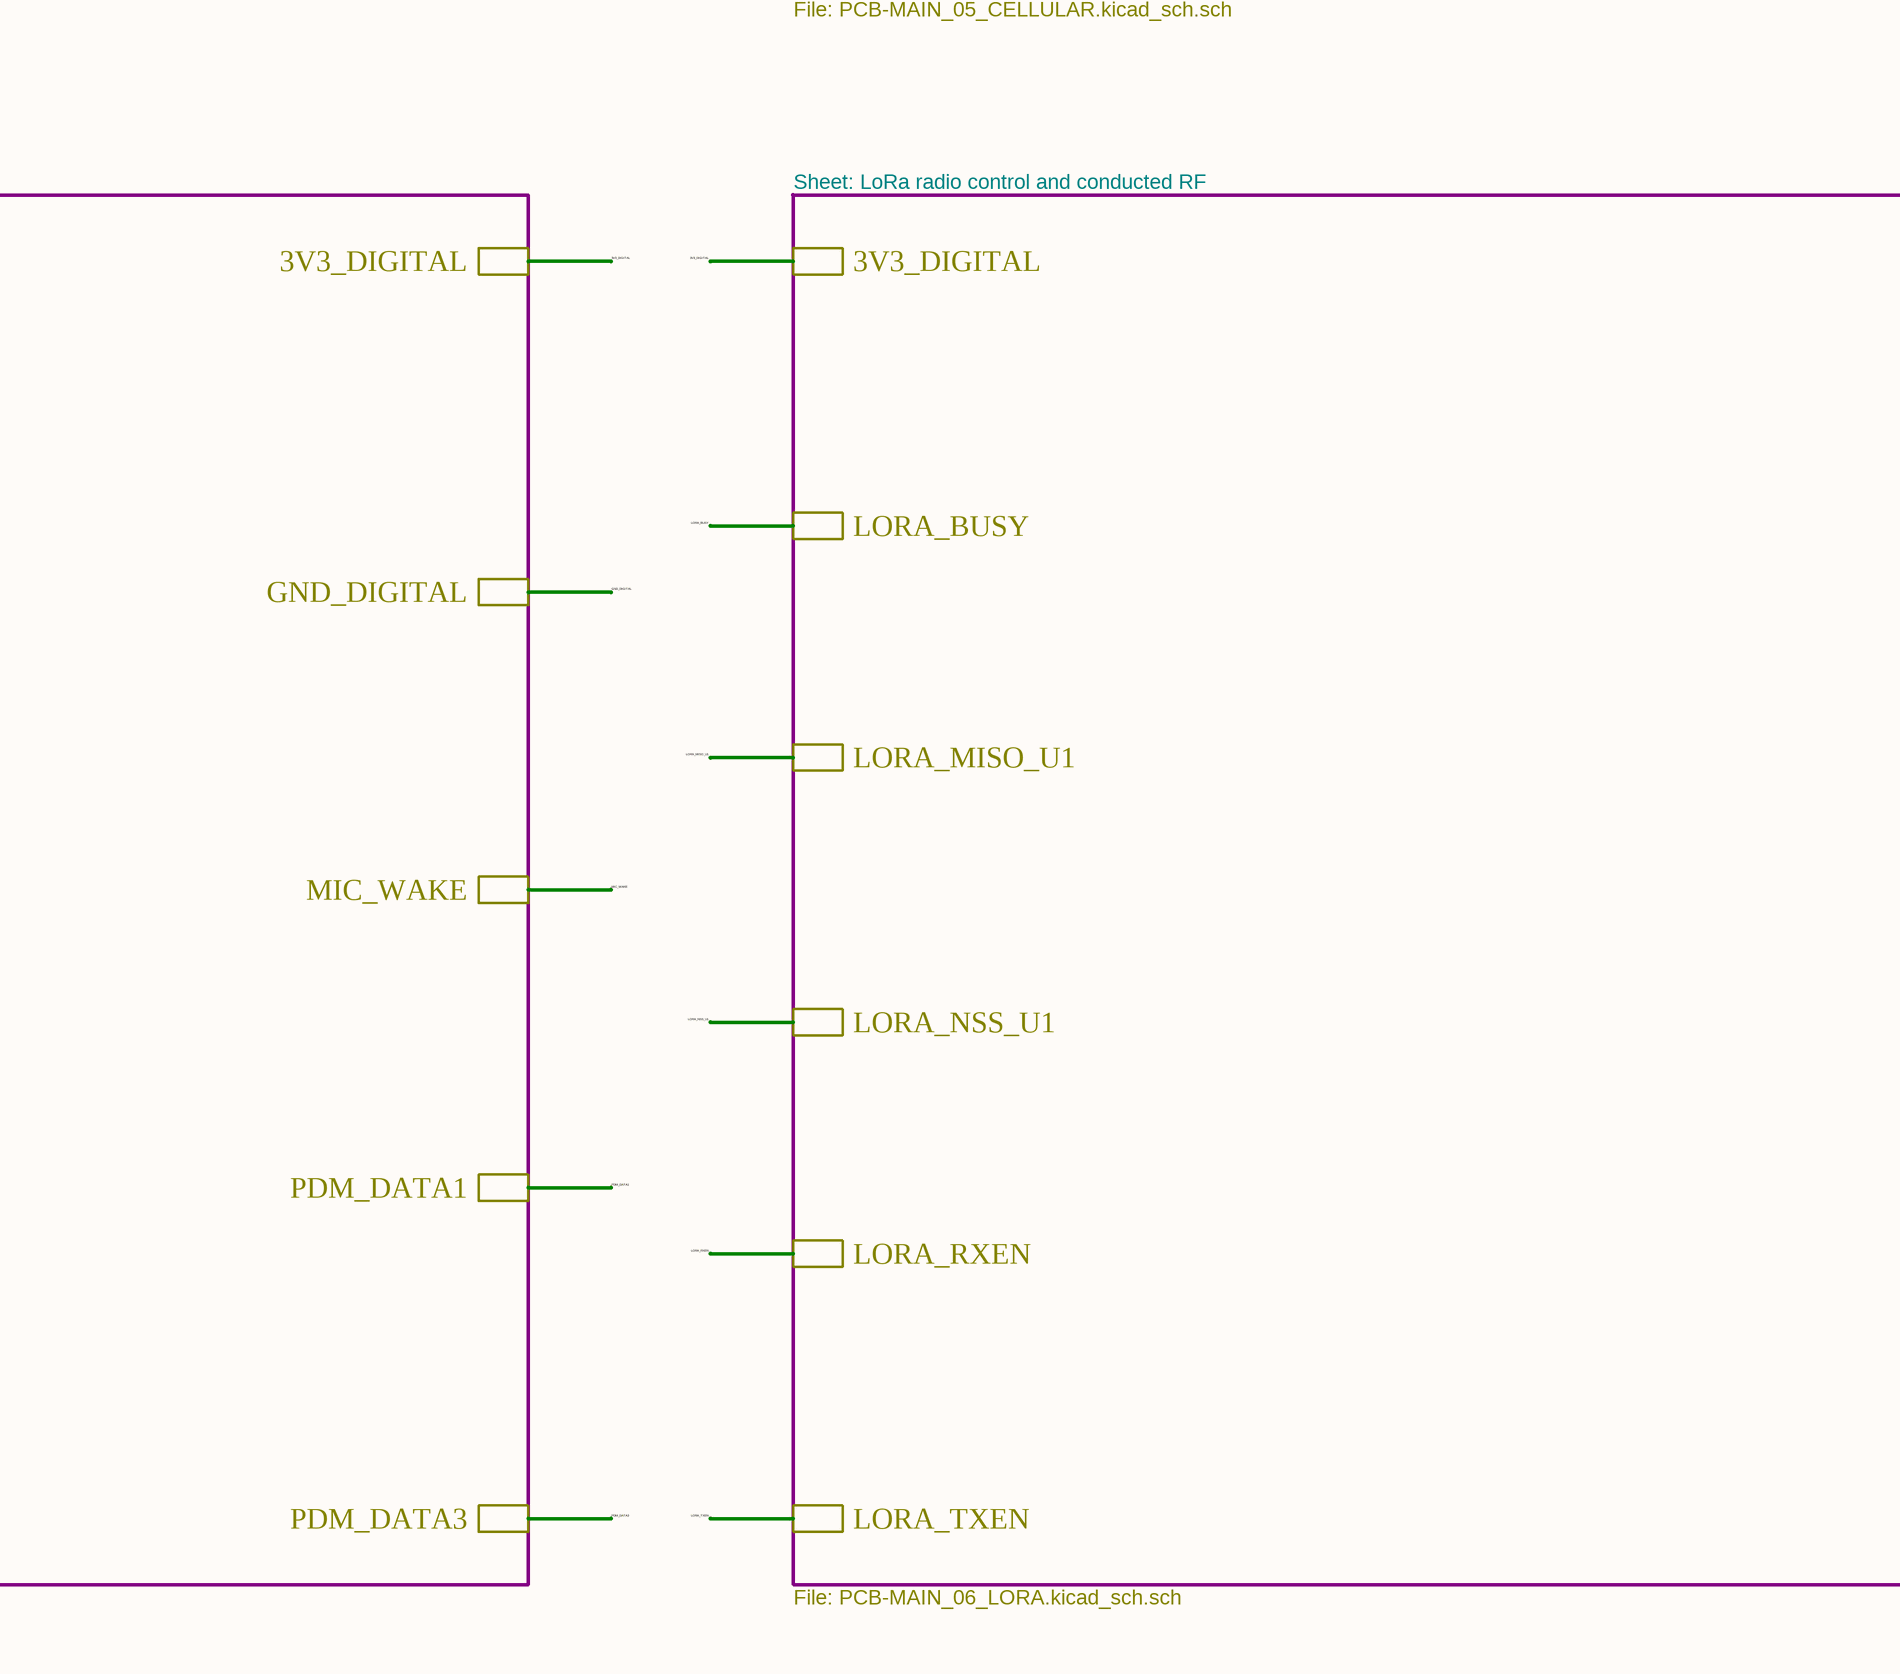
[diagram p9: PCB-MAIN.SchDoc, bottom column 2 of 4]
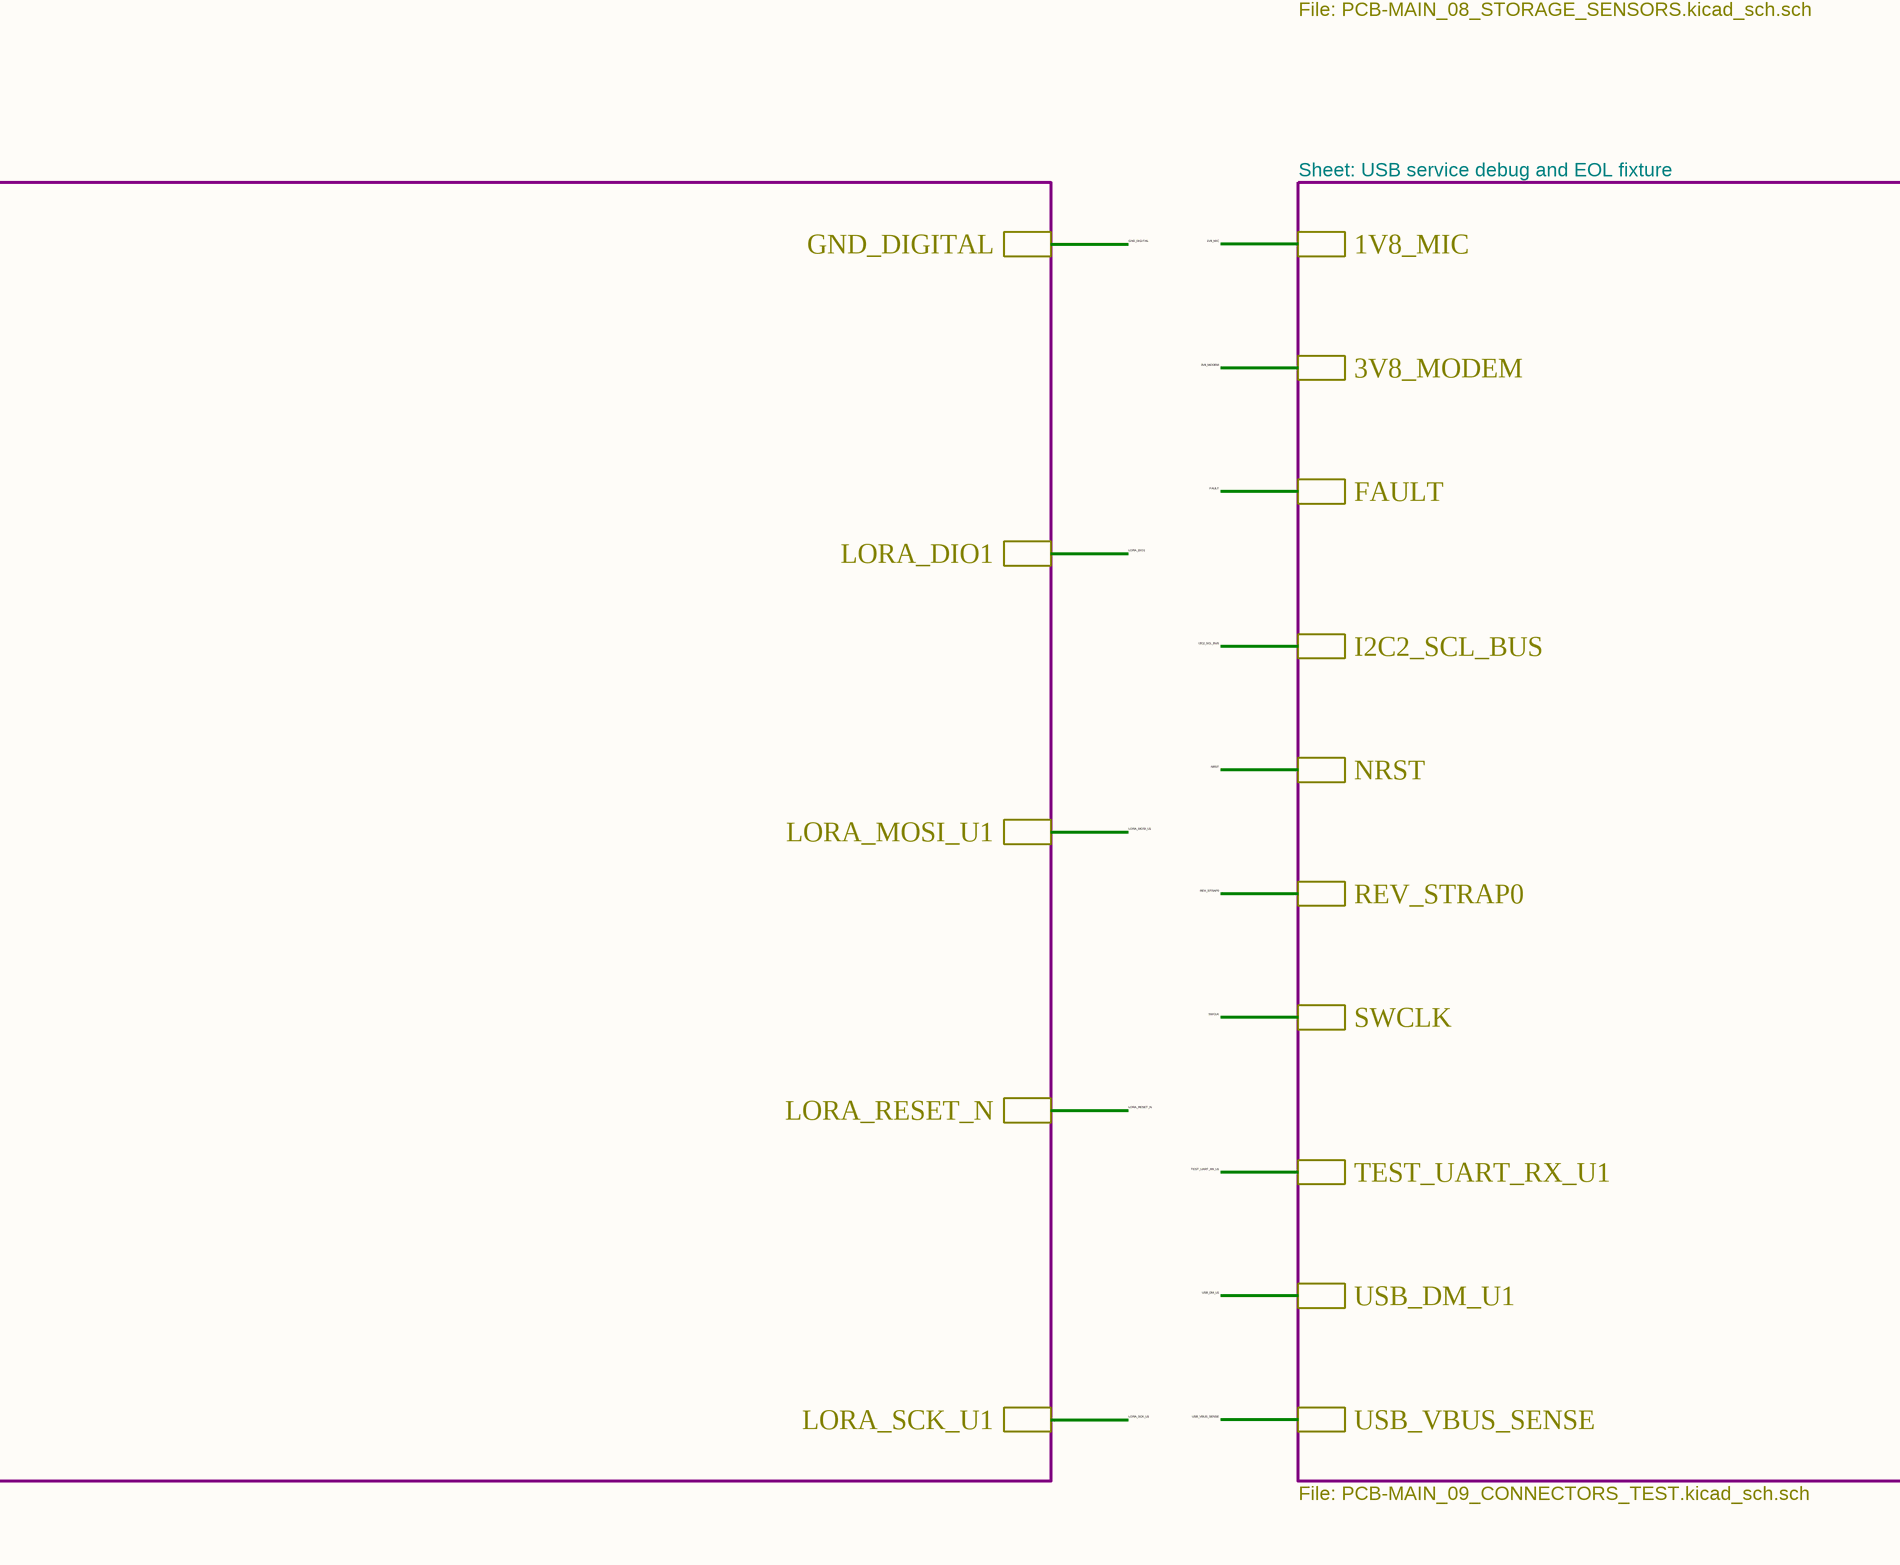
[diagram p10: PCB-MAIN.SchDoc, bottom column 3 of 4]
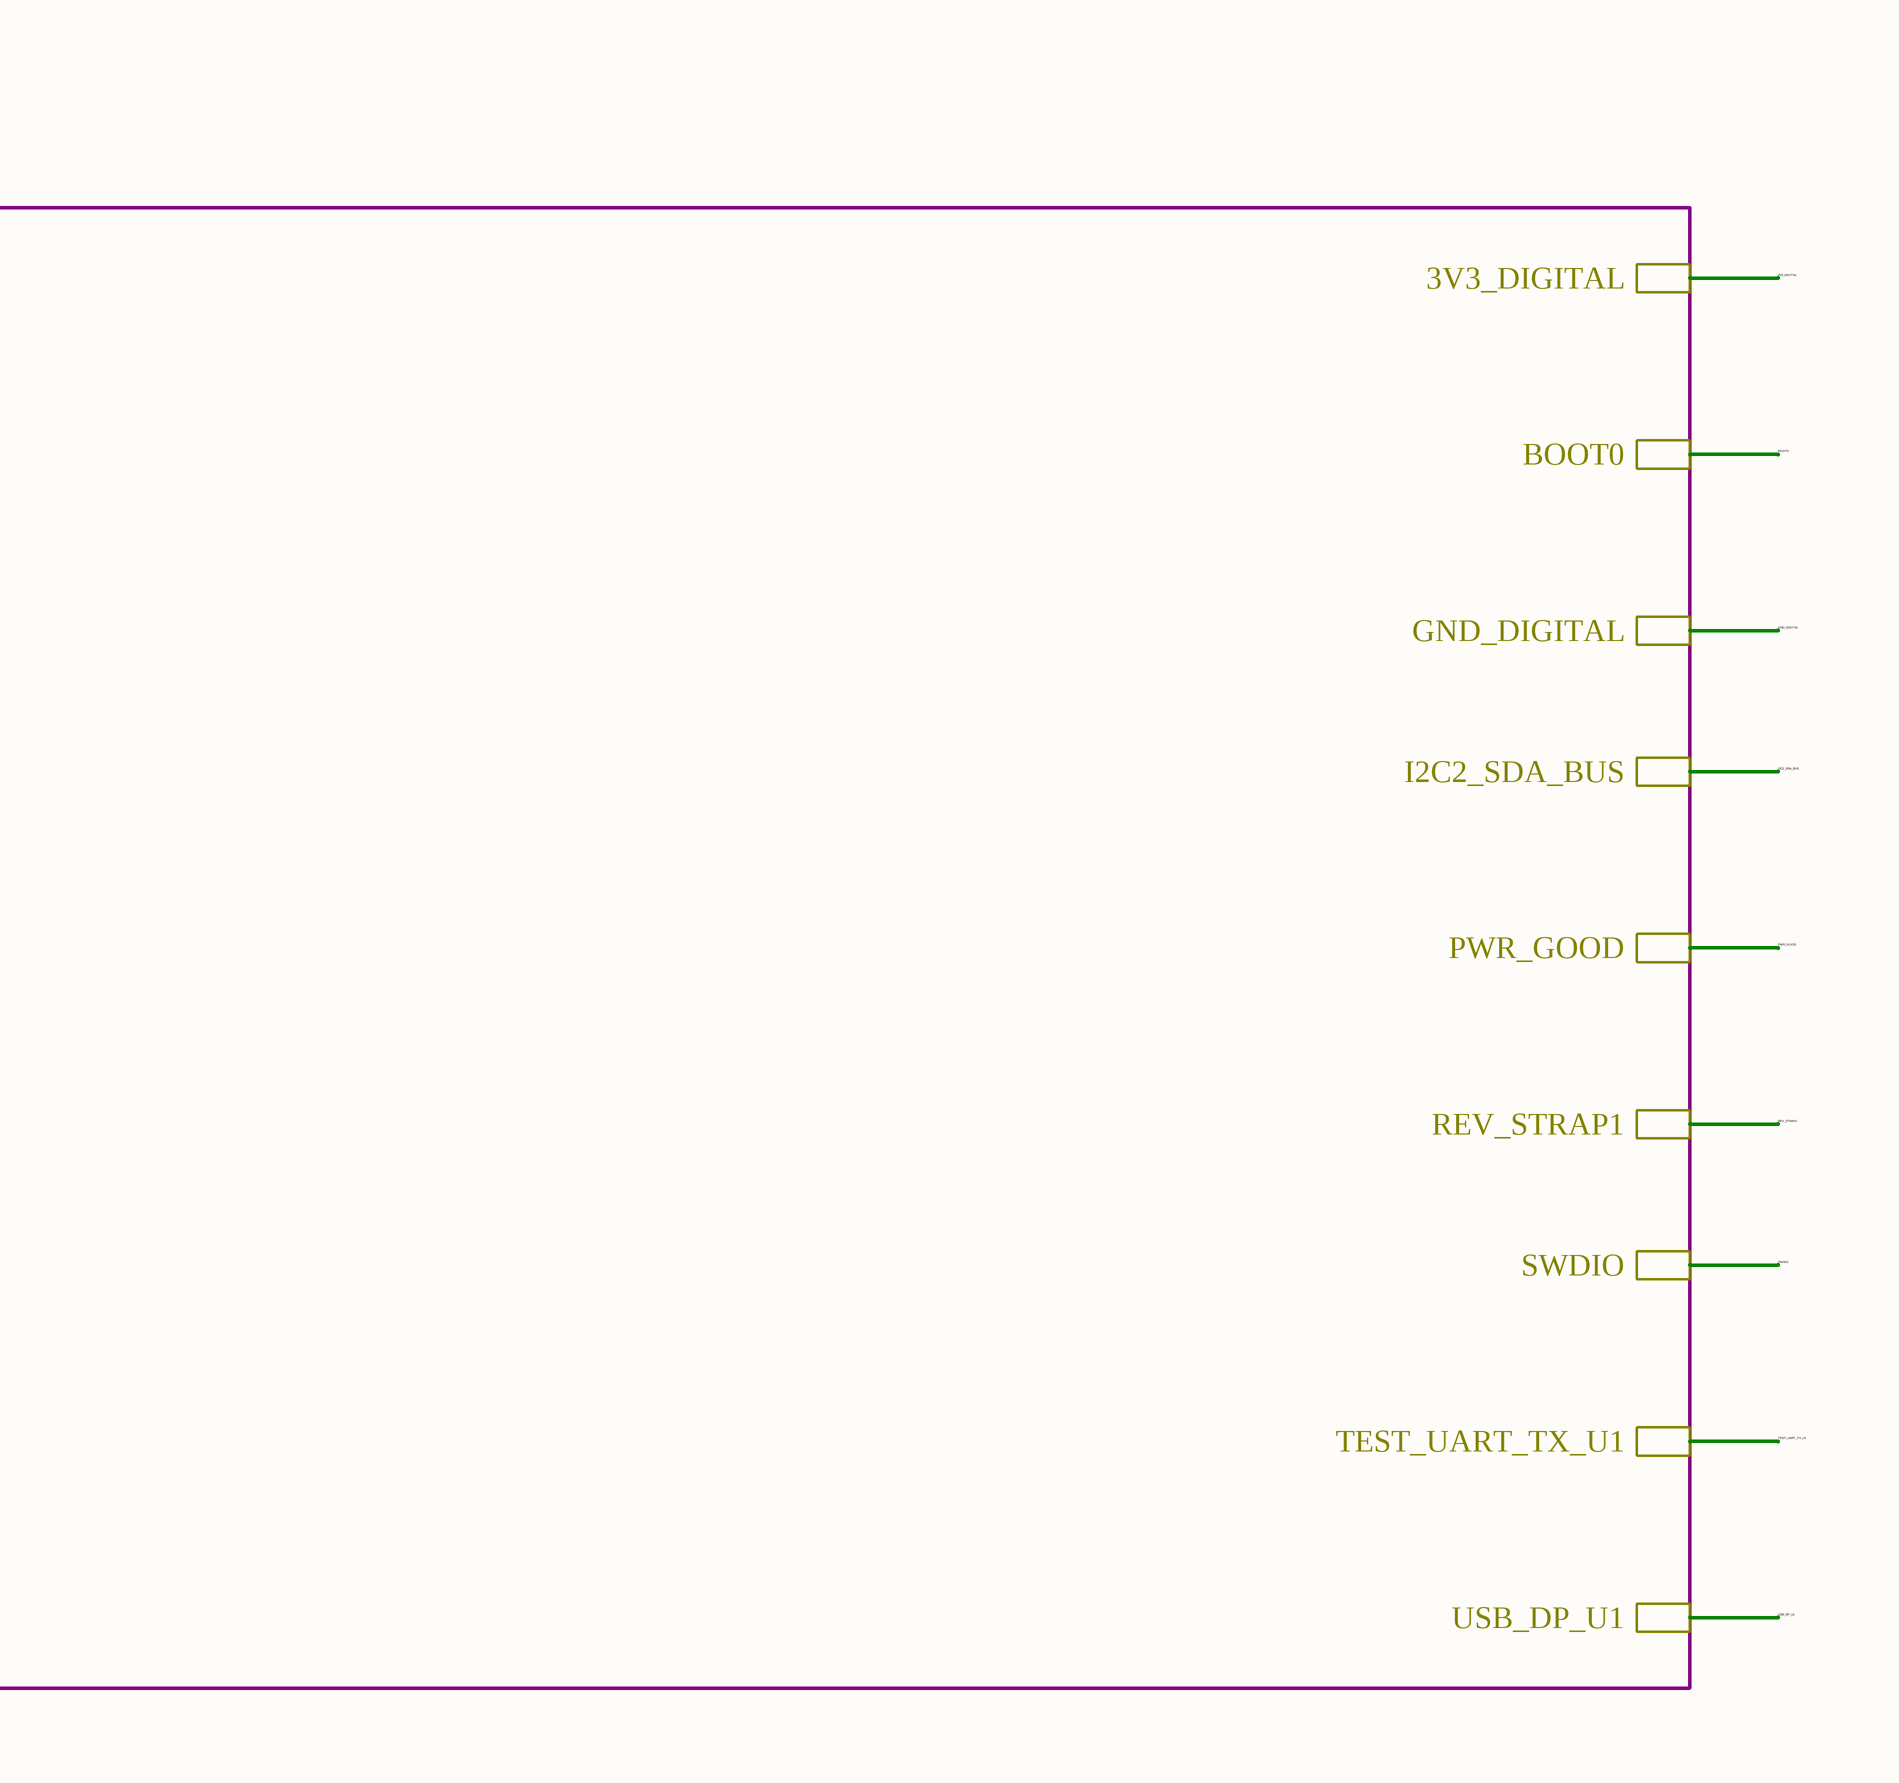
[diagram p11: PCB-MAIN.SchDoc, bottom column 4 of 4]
10 sheets, 248 parts. Net scope: strictly hierarchical (ports join the sheet entries above them; power ports are local).
Board file: PCB-MAIN.PcbDoc
Sheets:
  PCB-MAIN.SchDoc
    Power entry and rail interface = PCB-MAIN_01_POWER.SchDoc
    MCU clocks reset and straps = PCB-MAIN_02_MCU.SchDoc
    PDM audio AAD and microphone harnesses = PCB-MAIN_03_AUDIO.SchDoc
    GNSS timing antenna and supervisor = PCB-MAIN_04_GNSS.SchDoc
    Cellular modem dual SIM and recovery = PCB-MAIN_05_CELLULAR.SchDoc
    LoRa radio control and conducted RF = PCB-MAIN_06_LORA.SchDoc
    BLE module reset DFU and SWD = PCB-MAIN_07_BLE.SchDoc
    Storage sensors microSD and tamper = PCB-MAIN_08_STORAGE_SENSORS.SchDoc
    USB service debug and EOL fixture = PCB-MAIN_09_CONNECTORS_TEST.SchDoc

## Sheet PCB-MAIN.SchDoc
size 594 x 420 mm

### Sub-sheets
BLE module reset DFU and SWD = PCB-MAIN_07_BLE.SchDoc: 3V3_DIGITAL, BLE_EN, BLE_TX_U1, BLE_DFU_REQ, BLE_RX_U1, GND_DIGITAL
Cellular modem dual SIM and recovery = PCB-MAIN_05_CELLULAR.SchDoc: 3V3_DIGITAL, CELL_DTR_U16, CELL_RESET_N_CMD, CELL_RX_U16, CELL_TX_U16, SIM1_DET, SIM_MUX_EN, 3V8_MODEM, CELL_PWRKEY_CMD, CELL_RI_U16, CELL_STATUS_U16, GND_MODEM, SIM2_DET, SIM_MUX_SEL
GNSS timing antenna and supervisor = PCB-MAIN_04_GNSS.SchDoc: 3V3_DIGITAL, GNSS_PPS_U1, GNSS_TX_U1, GND_DIGITAL, GNSS_RX_U1
LoRa radio control and conducted RF = PCB-MAIN_06_LORA.SchDoc: 3V3_DIGITAL, LORA_BUSY, LORA_MISO_U1, LORA_NSS_U1, LORA_RXEN, LORA_TXEN, GND_DIGITAL, LORA_DIO1, LORA_MOSI_U1, LORA_RESET_N, LORA_SCK_U1
MCU clocks reset and straps = PCB-MAIN_02_MCU.SchDoc: 3V3_DIGITAL, ACCEL_INT, BLE_EN, BLE_TX_U1, CELL_DTR_U16, CELL_RESET_N_CMD, CELL_RX_U16, CELL_TX_U16, EN_MODEM, GNSS_PPS_U1, GNSS_TX_U1, I2C2_SDA_U1, LORA_DIO1, LORA_MOSI_U1, LORA_RESET_N, LORA_SCK_U1, MIC_WAKE, NOR_IO0_U1, NOR_IO2_U1, NOR_NCS_U2, PDM_CLK, PDM_DATA2, PDM_DATA4, PWR_GOOD, REV_STRAP1, SD_CMD_U1, SD_D1_U1, SD_D3_U1, SIM1_DET, SIM_MUX_EN, SWCLK, TAMPER_IN_U1, TEST_UART_TX_U1, USB_DP_U1, AAD_CFG, BLE_DFU_REQ, BLE_RX_U1, BOOT0, CELL_PWRKEY_CMD, CELL_RI_U16, CELL_STATUS_U16, EN_AUX, GND_DIGITAL, GNSS_RX_U1, I2C2_SCL_U1, LORA_BUSY, LORA_MISO_U1, LORA_NSS_U1, LORA_RXEN, LORA_TXEN, NOR_CLK_U1, NOR_IO1_U1, NOR_IO3_U1, NRST, PDM_DATA1, PDM_DATA3, PWR_FAULT, REV_STRAP0, SD_CK_U1, SD_D0_U1, SD_D2_U1, SD_DET, SIM2_DET, SIM_MUX_SEL, SWDIO, TEST_UART_RX_U1, USB_DM_U1, USB_VBUS_SENSE
PDM audio AAD and microphone harnesses = PCB-MAIN_03_AUDIO.SchDoc: 1V8_MIC, AAD_CFG, GND_MIC, PDM_CLK, PDM_DATA2, PDM_DATA4, 3V3_DIGITAL, GND_DIGITAL, MIC_WAKE, PDM_DATA1, PDM_DATA3
Power entry and rail interface = PCB-MAIN_01_POWER.SchDoc: 1V8_MIC, 3V8_MODEM, EN_MODEM, GND_DIGITAL, GND_MODEM, I2C2_SDA_BUS, PWR_GOOD, 3V3_DIGITAL, EN_AUX, FAULT, GND_MIC, I2C2_SCL_BUS, PWR_FAULT
Storage sensors microSD and tamper = PCB-MAIN_08_STORAGE_SENSORS.SchDoc: 3V3_DIGITAL, GND_DIGITAL, I2C2_SCL_U1, I2C2_SDA_U1, NOR_IO0_U1, NOR_IO2_U1, NOR_NCS_U2, SD_CMD_U1, SD_D1_U1, SD_D3_U1, TAMPER_IN_U1, ACCEL_INT, I2C2_SCL_BUS, I2C2_SDA_BUS, NOR_CLK_U1, NOR_IO1_U1, NOR_IO3_U1, SD_CK_U1, SD_D0_U1, SD_D2_U1, SD_DET
USB service debug and EOL fixture = PCB-MAIN_09_CONNECTORS_TEST.SchDoc: 1V8_MIC, 3V8_MODEM, FAULT, I2C2_SCL_BUS, NRST, REV_STRAP0, SWCLK, TEST_UART_RX_U1, USB_DM_U1, USB_VBUS_SENSE, 3V3_DIGITAL, BOOT0, GND_DIGITAL, I2C2_SDA_BUS, PWR_GOOD, REV_STRAP1, SWDIO, TEST_UART_TX_U1, USB_DP_U1

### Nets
1V8_MIC: sheet Power entry and rail interface/1V8_MIC, sheet PDM audio AAD and microphone harnesses/1V8_MIC, sheet USB service debug and EOL fixture/1V8_MIC
3V3_DIGITAL: sheet Power entry and rail interface/3V3_DIGITAL, sheet MCU clocks reset and straps/3V3_DIGITAL, sheet PDM audio AAD and microphone harnesses/3V3_DIGITAL, sheet GNSS timing antenna and supervisor/3V3_DIGITAL, sheet Cellular modem dual SIM and recovery/3V3_DIGITAL, sheet LoRa radio control and conducted RF/3V3_DIGITAL, sheet BLE module reset DFU and SWD/3V3_DIGITAL, sheet Storage sensors microSD and tamper/3V3_DIGITAL, sheet USB service debug and EOL fixture/3V3_DIGITAL
3V8_MODEM: sheet Power entry and rail interface/3V8_MODEM, sheet Cellular modem dual SIM and recovery/3V8_MODEM, sheet USB service debug and EOL fixture/3V8_MODEM
AAD_CFG: sheet MCU clocks reset and straps/AAD_CFG, sheet PDM audio AAD and microphone harnesses/AAD_CFG
ACCEL_INT: sheet MCU clocks reset and straps/ACCEL_INT, sheet Storage sensors microSD and tamper/ACCEL_INT
BLE_DFU_REQ: sheet MCU clocks reset and straps/BLE_DFU_REQ, sheet BLE module reset DFU and SWD/BLE_DFU_REQ
BLE_EN: sheet MCU clocks reset and straps/BLE_EN, sheet BLE module reset DFU and SWD/BLE_EN
BLE_RX_U1: sheet MCU clocks reset and straps/BLE_RX_U1, sheet BLE module reset DFU and SWD/BLE_RX_U1
BLE_TX_U1: sheet MCU clocks reset and straps/BLE_TX_U1, sheet BLE module reset DFU and SWD/BLE_TX_U1
BOOT0: sheet MCU clocks reset and straps/BOOT0, sheet USB service debug and EOL fixture/BOOT0
CELL_DTR_U16: sheet MCU clocks reset and straps/CELL_DTR_U16, sheet Cellular modem dual SIM and recovery/CELL_DTR_U16
CELL_PWRKEY_CMD: sheet MCU clocks reset and straps/CELL_PWRKEY_CMD, sheet Cellular modem dual SIM and recovery/CELL_PWRKEY_CMD
CELL_RESET_N_CMD: sheet MCU clocks reset and straps/CELL_RESET_N_CMD, sheet Cellular modem dual SIM and recovery/CELL_RESET_N_CMD
CELL_RI_U16: sheet MCU clocks reset and straps/CELL_RI_U16, sheet Cellular modem dual SIM and recovery/CELL_RI_U16
CELL_RX_U16: sheet MCU clocks reset and straps/CELL_RX_U16, sheet Cellular modem dual SIM and recovery/CELL_RX_U16
CELL_STATUS_U16: sheet MCU clocks reset and straps/CELL_STATUS_U16, sheet Cellular modem dual SIM and recovery/CELL_STATUS_U16
CELL_TX_U16: sheet MCU clocks reset and straps/CELL_TX_U16, sheet Cellular modem dual SIM and recovery/CELL_TX_U16
EN_AUX: sheet Power entry and rail interface/EN_AUX, sheet MCU clocks reset and straps/EN_AUX
EN_MODEM: sheet Power entry and rail interface/EN_MODEM, sheet MCU clocks reset and straps/EN_MODEM
FAULT: sheet Power entry and rail interface/FAULT, sheet USB service debug and EOL fixture/FAULT
GND_DIGITAL: sheet Power entry and rail interface/GND_DIGITAL, sheet MCU clocks reset and straps/GND_DIGITAL, sheet PDM audio AAD and microphone harnesses/GND_DIGITAL, sheet GNSS timing antenna and supervisor/GND_DIGITAL, sheet LoRa radio control and conducted RF/GND_DIGITAL, sheet BLE module reset DFU and SWD/GND_DIGITAL, sheet Storage sensors microSD and tamper/GND_DIGITAL, sheet USB service debug and EOL fixture/GND_DIGITAL
GND_MIC: sheet Power entry and rail interface/GND_MIC, sheet PDM audio AAD and microphone harnesses/GND_MIC
GND_MODEM: sheet Power entry and rail interface/GND_MODEM, sheet Cellular modem dual SIM and recovery/GND_MODEM
GNSS_PPS_U1: sheet MCU clocks reset and straps/GNSS_PPS_U1, sheet GNSS timing antenna and supervisor/GNSS_PPS_U1
GNSS_RX_U1: sheet MCU clocks reset and straps/GNSS_RX_U1, sheet GNSS timing antenna and supervisor/GNSS_RX_U1
GNSS_TX_U1: sheet MCU clocks reset and straps/GNSS_TX_U1, sheet GNSS timing antenna and supervisor/GNSS_TX_U1
I2C2_SCL_BUS: sheet Power entry and rail interface/I2C2_SCL_BUS, sheet Storage sensors microSD and tamper/I2C2_SCL_BUS, sheet USB service debug and EOL fixture/I2C2_SCL_BUS
I2C2_SCL_U1: sheet MCU clocks reset and straps/I2C2_SCL_U1, sheet Storage sensors microSD and tamper/I2C2_SCL_U1
I2C2_SDA_BUS: sheet Power entry and rail interface/I2C2_SDA_BUS, sheet Storage sensors microSD and tamper/I2C2_SDA_BUS, sheet USB service debug and EOL fixture/I2C2_SDA_BUS
I2C2_SDA_U1: sheet MCU clocks reset and straps/I2C2_SDA_U1, sheet Storage sensors microSD and tamper/I2C2_SDA_U1
LORA_BUSY: sheet MCU clocks reset and straps/LORA_BUSY, sheet LoRa radio control and conducted RF/LORA_BUSY
LORA_DIO1: sheet MCU clocks reset and straps/LORA_DIO1, sheet LoRa radio control and conducted RF/LORA_DIO1
LORA_MISO_U1: sheet MCU clocks reset and straps/LORA_MISO_U1, sheet LoRa radio control and conducted RF/LORA_MISO_U1
LORA_MOSI_U1: sheet MCU clocks reset and straps/LORA_MOSI_U1, sheet LoRa radio control and conducted RF/LORA_MOSI_U1
LORA_NSS_U1: sheet MCU clocks reset and straps/LORA_NSS_U1, sheet LoRa radio control and conducted RF/LORA_NSS_U1
LORA_RESET_N: sheet MCU clocks reset and straps/LORA_RESET_N, sheet LoRa radio control and conducted RF/LORA_RESET_N
LORA_RXEN: sheet MCU clocks reset and straps/LORA_RXEN, sheet LoRa radio control and conducted RF/LORA_RXEN
LORA_SCK_U1: sheet MCU clocks reset and straps/LORA_SCK_U1, sheet LoRa radio control and conducted RF/LORA_SCK_U1
LORA_TXEN: sheet MCU clocks reset and straps/LORA_TXEN, sheet LoRa radio control and conducted RF/LORA_TXEN
MIC_WAKE: sheet MCU clocks reset and straps/MIC_WAKE, sheet PDM audio AAD and microphone harnesses/MIC_WAKE
NOR_CLK_U1: sheet MCU clocks reset and straps/NOR_CLK_U1, sheet Storage sensors microSD and tamper/NOR_CLK_U1
NOR_IO0_U1: sheet MCU clocks reset and straps/NOR_IO0_U1, sheet Storage sensors microSD and tamper/NOR_IO0_U1
NOR_IO1_U1: sheet MCU clocks reset and straps/NOR_IO1_U1, sheet Storage sensors microSD and tamper/NOR_IO1_U1
NOR_IO2_U1: sheet MCU clocks reset and straps/NOR_IO2_U1, sheet Storage sensors microSD and tamper/NOR_IO2_U1
NOR_IO3_U1: sheet MCU clocks reset and straps/NOR_IO3_U1, sheet Storage sensors microSD and tamper/NOR_IO3_U1
NOR_NCS_U2: sheet MCU clocks reset and straps/NOR_NCS_U2, sheet Storage sensors microSD and tamper/NOR_NCS_U2
NRST: sheet MCU clocks reset and straps/NRST, sheet USB service debug and EOL fixture/NRST
PDM_CLK: sheet MCU clocks reset and straps/PDM_CLK, sheet PDM audio AAD and microphone harnesses/PDM_CLK
PDM_DATA1: sheet MCU clocks reset and straps/PDM_DATA1, sheet PDM audio AAD and microphone harnesses/PDM_DATA1
PDM_DATA2: sheet MCU clocks reset and straps/PDM_DATA2, sheet PDM audio AAD and microphone harnesses/PDM_DATA2
PDM_DATA3: sheet MCU clocks reset and straps/PDM_DATA3, sheet PDM audio AAD and microphone harnesses/PDM_DATA3
PDM_DATA4: sheet MCU clocks reset and straps/PDM_DATA4, sheet PDM audio AAD and microphone harnesses/PDM_DATA4
PWR_FAULT: sheet Power entry and rail interface/PWR_FAULT, sheet MCU clocks reset and straps/PWR_FAULT
PWR_GOOD: sheet Power entry and rail interface/PWR_GOOD, sheet MCU clocks reset and straps/PWR_GOOD, sheet USB service debug and EOL fixture/PWR_GOOD
REV_STRAP0: sheet MCU clocks reset and straps/REV_STRAP0, sheet USB service debug and EOL fixture/REV_STRAP0
REV_STRAP1: sheet MCU clocks reset and straps/REV_STRAP1, sheet USB service debug and EOL fixture/REV_STRAP1
SD_CK_U1: sheet MCU clocks reset and straps/SD_CK_U1, sheet Storage sensors microSD and tamper/SD_CK_U1
SD_CMD_U1: sheet MCU clocks reset and straps/SD_CMD_U1, sheet Storage sensors microSD and tamper/SD_CMD_U1
SD_D0_U1: sheet MCU clocks reset and straps/SD_D0_U1, sheet Storage sensors microSD and tamper/SD_D0_U1
SD_D1_U1: sheet MCU clocks reset and straps/SD_D1_U1, sheet Storage sensors microSD and tamper/SD_D1_U1
SD_D2_U1: sheet MCU clocks reset and straps/SD_D2_U1, sheet Storage sensors microSD and tamper/SD_D2_U1
SD_D3_U1: sheet MCU clocks reset and straps/SD_D3_U1, sheet Storage sensors microSD and tamper/SD_D3_U1
SD_DET: sheet MCU clocks reset and straps/SD_DET, sheet Storage sensors microSD and tamper/SD_DET
SIM1_DET: sheet MCU clocks reset and straps/SIM1_DET, sheet Cellular modem dual SIM and recovery/SIM1_DET
SIM2_DET: sheet MCU clocks reset and straps/SIM2_DET, sheet Cellular modem dual SIM and recovery/SIM2_DET
SIM_MUX_EN: sheet MCU clocks reset and straps/SIM_MUX_EN, sheet Cellular modem dual SIM and recovery/SIM_MUX_EN
SIM_MUX_SEL: sheet MCU clocks reset and straps/SIM_MUX_SEL, sheet Cellular modem dual SIM and recovery/SIM_MUX_SEL
SWCLK: sheet MCU clocks reset and straps/SWCLK, sheet USB service debug and EOL fixture/SWCLK
SWDIO: sheet MCU clocks reset and straps/SWDIO, sheet USB service debug and EOL fixture/SWDIO
TAMPER_IN_U1: sheet MCU clocks reset and straps/TAMPER_IN_U1, sheet Storage sensors microSD and tamper/TAMPER_IN_U1
TEST_UART_RX_U1: sheet MCU clocks reset and straps/TEST_UART_RX_U1, sheet USB service debug and EOL fixture/TEST_UART_RX_U1
TEST_UART_TX_U1: sheet MCU clocks reset and straps/TEST_UART_TX_U1, sheet USB service debug and EOL fixture/TEST_UART_TX_U1
USB_DM_U1: sheet MCU clocks reset and straps/USB_DM_U1, sheet USB service debug and EOL fixture/USB_DM_U1
USB_DP_U1: sheet MCU clocks reset and straps/USB_DP_U1, sheet USB service debug and EOL fixture/USB_DP_U1
USB_VBUS_SENSE: sheet MCU clocks reset and straps/USB_VBUS_SENSE, sheet USB service debug and EOL fixture/USB_VBUS_SENSE

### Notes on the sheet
- Hierarchy-only engineering candidate. Signed Review-A pin/net authority is retained; routing, DRC, DFM, Review B and manufacture remain prohibited.
- Sheet: Power entry and rail interface
- Sheet: GNSS timing antenna and supervisor
- Sheet: BLE module reset DFU and SWD
- File: PCB-MAIN_01_POWER.kicad_sch.sch
- File: PCB-MAIN_04_GNSS.kicad_sch.sch
- File: PCB-MAIN_07_BLE.kicad_sch.sch
- Sheet: MCU clocks reset and straps
- Sheet: Cellular modem dual SIM and recovery
- Sheet: Storage sensors microSD and tamper
- File: PCB-MAIN_02_MCU.kicad_sch.sch
- File: PCB-MAIN_05_CELLULAR.kicad_sch.sch
- File: PCB-MAIN_08_STORAGE_SENSORS.kicad_sch.sch
- Sheet: PDM audio AAD and microphone harnesses
- Sheet: LoRa radio control and conducted RF
- Sheet: USB service debug and EOL fixture
- File: PCB-MAIN_03_AUDIO.kicad_sch.sch
- File: PCB-MAIN_06_LORA.kicad_sch.sch
- File: PCB-MAIN_09_CONNECTORS_TEST.kicad_sch.sch

## Sheet PCB-MAIN_01_POWER.SchDoc
size 594 x 420 mm
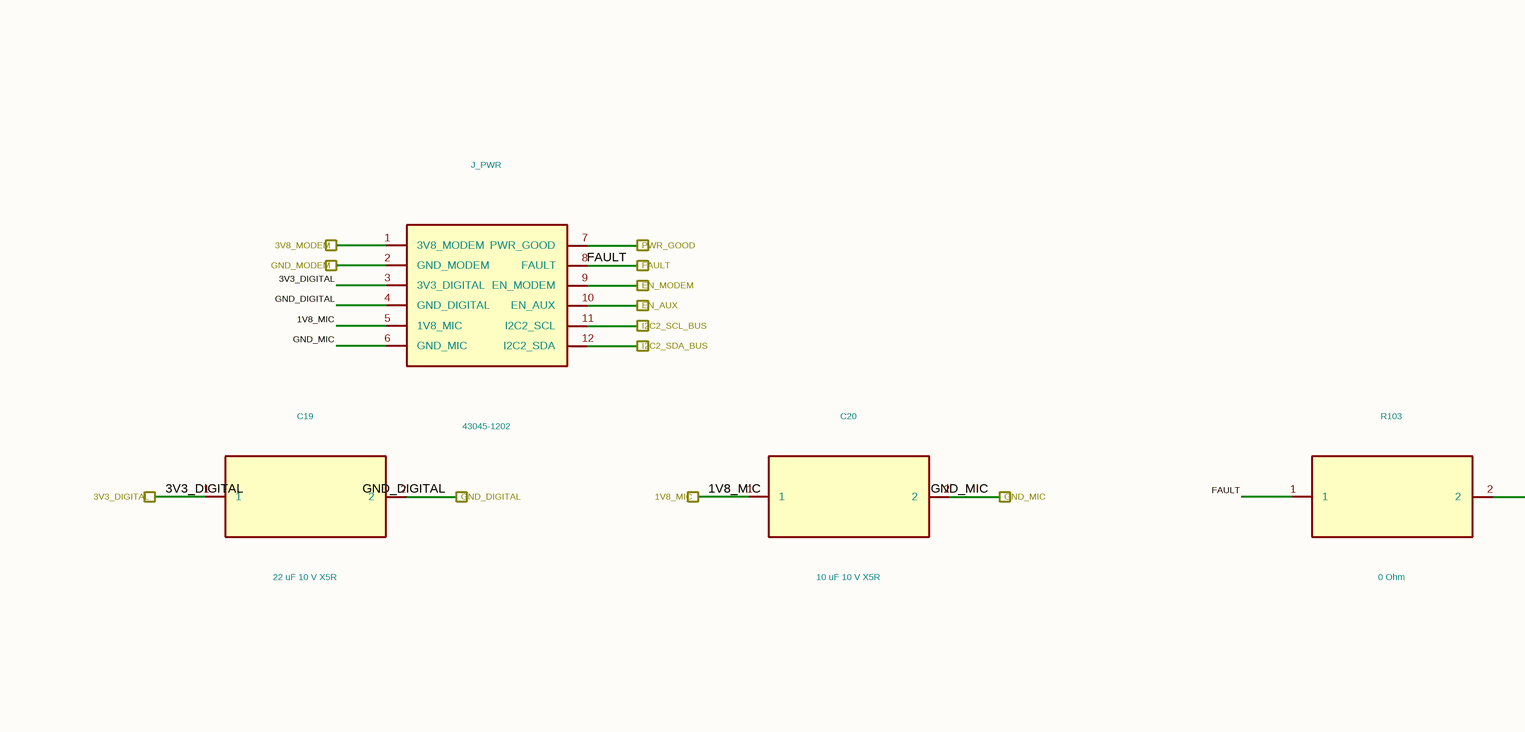
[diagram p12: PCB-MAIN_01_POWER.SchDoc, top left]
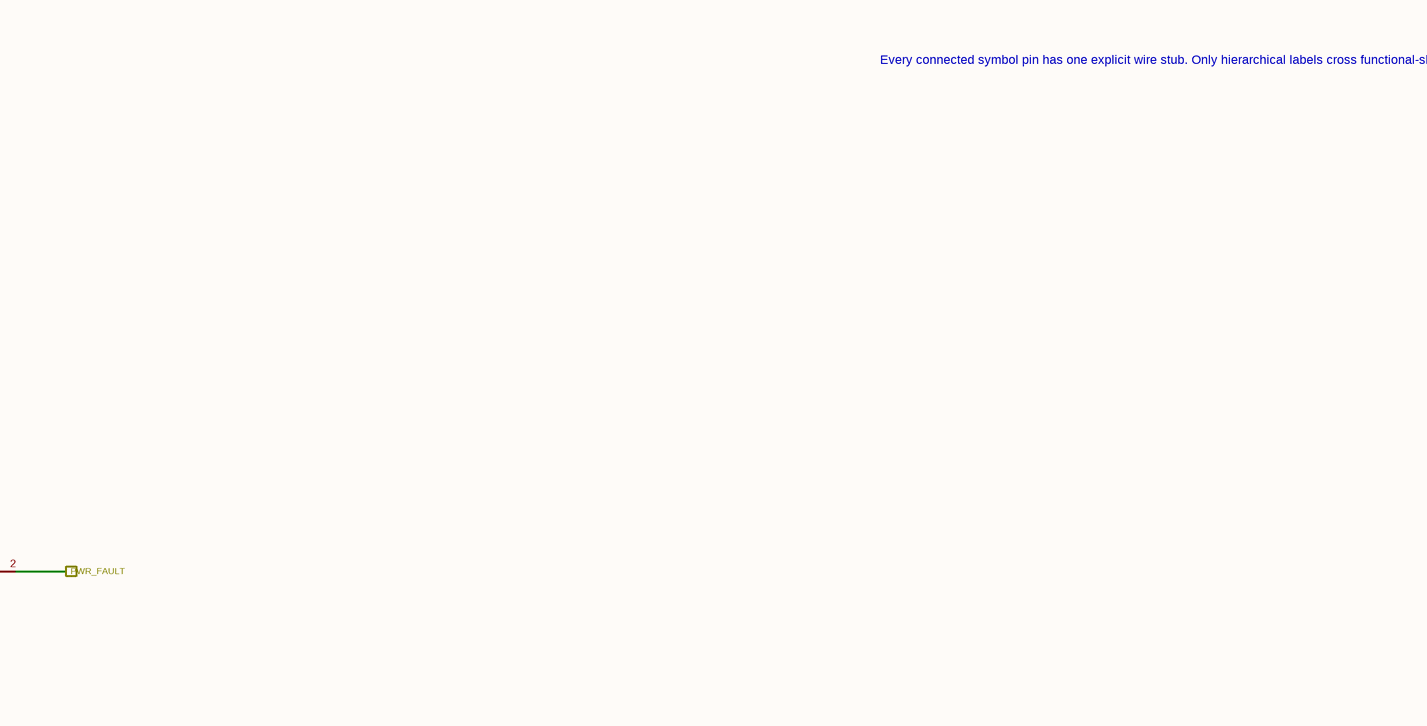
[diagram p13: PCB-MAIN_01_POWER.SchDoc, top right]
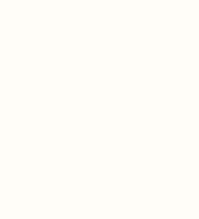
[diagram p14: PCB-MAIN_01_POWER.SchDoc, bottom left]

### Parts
C19  22 uF 10 V X5R  [C_0805_2012Metric]
C20  10 uF 10 V X5R  [C_0603_1608Metric]
J_PWR  43045-1202
R103  0 Ohm  [R_0402_1005Metric]

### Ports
1V8_MIC, 3V3_DIGITAL, 3V8_MODEM, EN_AUX, EN_MODEM, FAULT, GND_DIGITAL, GND_MIC, GND_MODEM, I2C2_SCL_BUS, I2C2_SDA_BUS, PWR_FAULT, PWR_GOOD

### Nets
1V8_MIC: C20.1 J_PWR.5(1V8_MIC) ; port 1V8_MIC
3V3_DIGITAL: C19.1 J_PWR.3(3V3_DIGITAL) ; port 3V3_DIGITAL
3V8_MODEM: J_PWR.1(3V8_MODEM) ; port 3V8_MODEM
EN_AUX: J_PWR.10(EN_AUX) ; port EN_AUX
EN_MODEM: J_PWR.9(EN_MODEM) ; port EN_MODEM
FAULT: J_PWR.8(FAULT) R103.1 ; port FAULT
GND_DIGITAL: C19.2 J_PWR.4(GND_DIGITAL) ; port GND_DIGITAL
GND_MIC: C20.2 J_PWR.6(GND_MIC) ; port GND_MIC
GND_MODEM: J_PWR.2(GND_MODEM) ; port GND_MODEM
I2C2_SCL_BUS: J_PWR.11(I2C2_SCL) ; port I2C2_SCL_BUS
I2C2_SDA_BUS: J_PWR.12(I2C2_SDA) ; port I2C2_SDA_BUS
PWR_FAULT: R103.2 ; port PWR_FAULT
PWR_GOOD: J_PWR.7(PWR_GOOD) ; port PWR_GOOD

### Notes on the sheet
- Every connected symbol pin has one explicit wire stub. Only hierarchical labels cross functional-sheet boundaries.

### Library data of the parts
C19 = C19_GRM21BR61A226ME44L: Manufacturer: Murata; Population: FITTED; Authority: PROJECT_MAIN_AUTH_010
C20 = C20_GRM188R61A106KE69D: Manufacturer: Murata; Population: FITTED; Authority: PROJECT_MAIN_AUTH_010
J_PWR = J_PWR_43045-1202: Manufacturer: Molex; Population: FITTED; Authority: HARNESS_LOGICAL_PINOUT_REV_A.csv
R103 = R103_ERJ-2GE0R00X: Manufacturer: Panasonic; Population: FITTED; Authority: PROJECT_MAIN_AUTH_010

## Sheet PCB-MAIN_02_MCU.SchDoc
size 594 x 420 mm
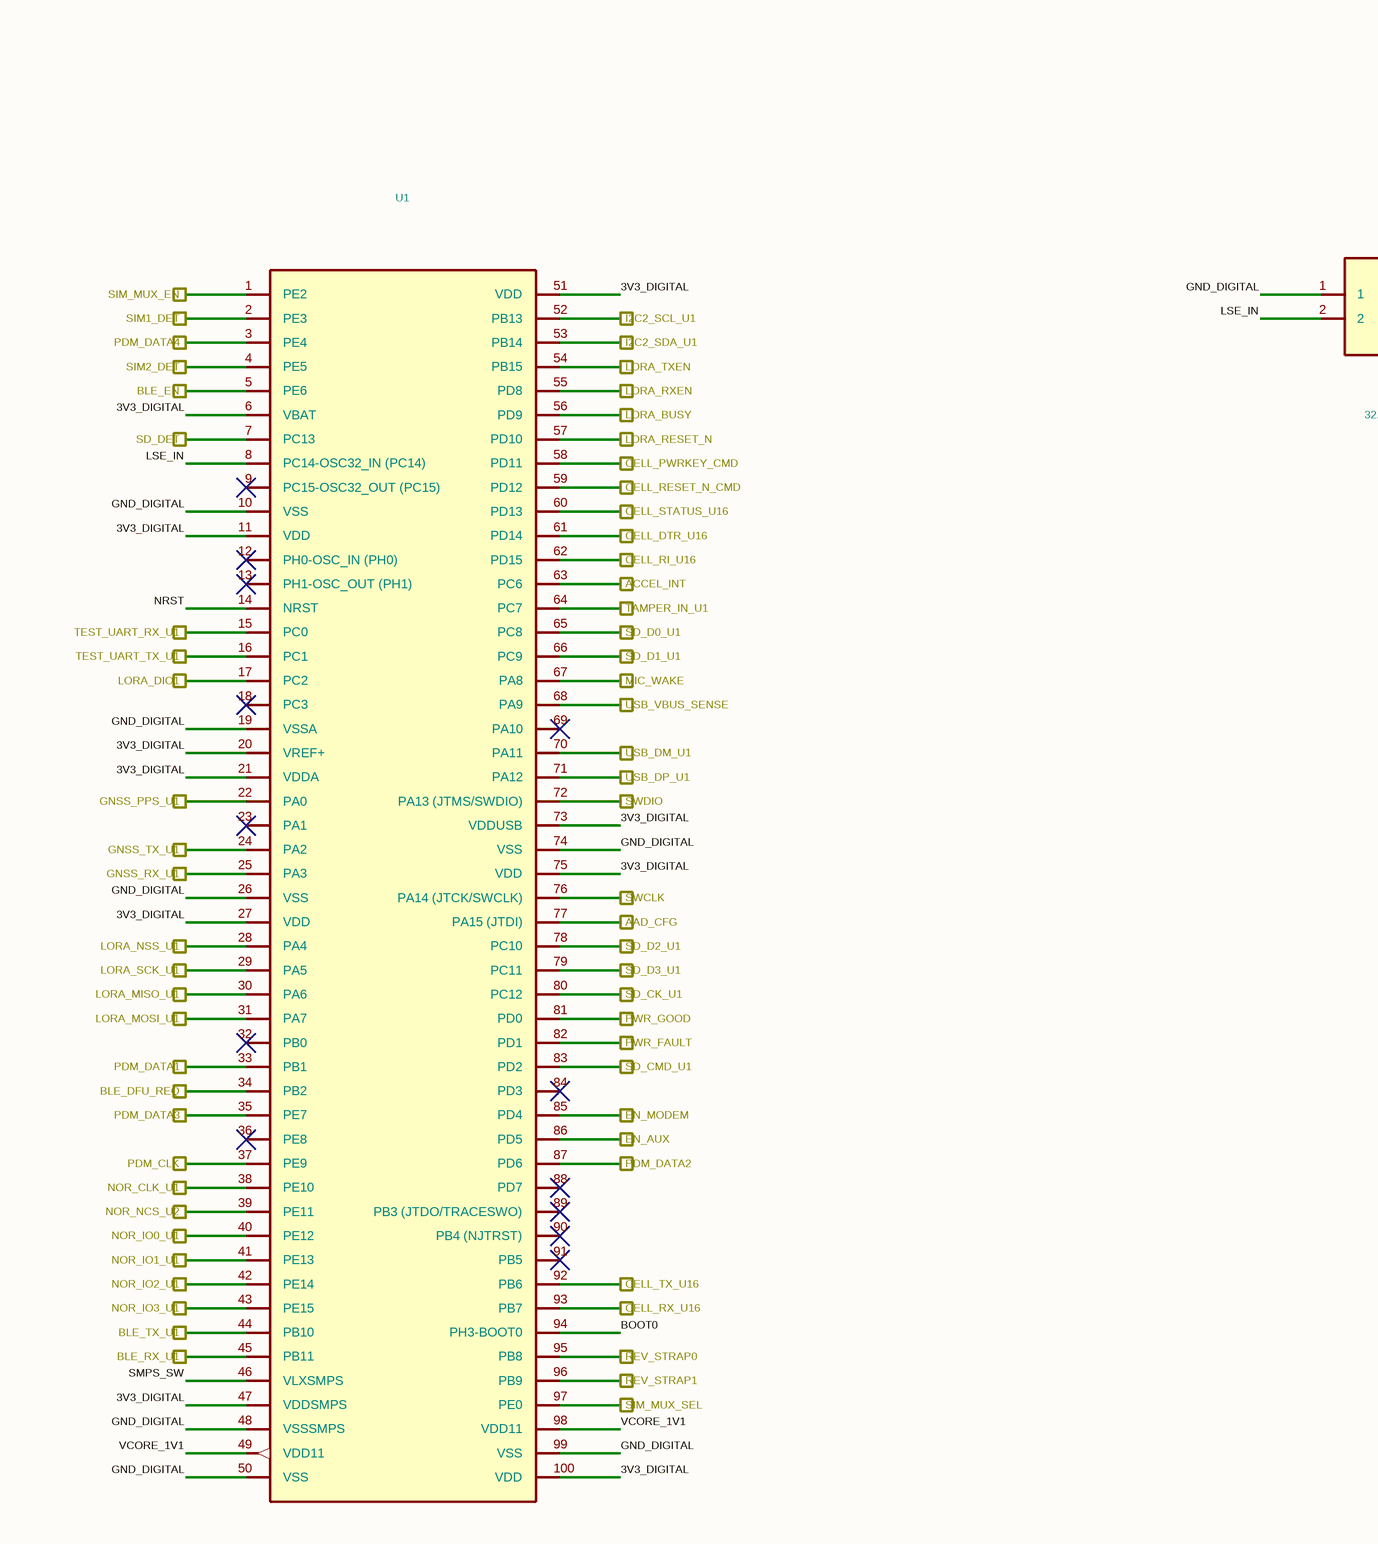
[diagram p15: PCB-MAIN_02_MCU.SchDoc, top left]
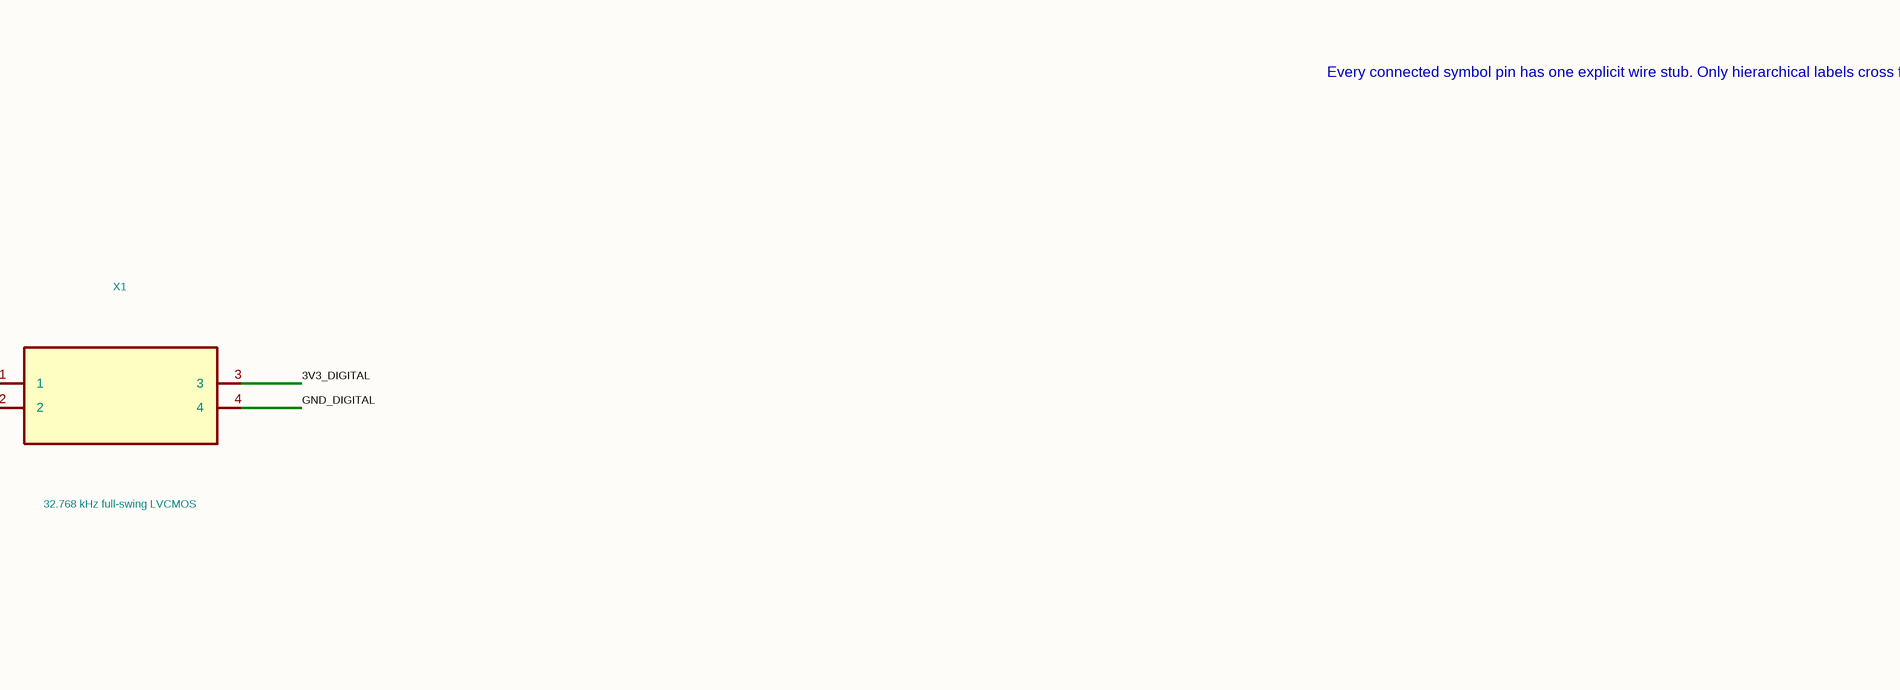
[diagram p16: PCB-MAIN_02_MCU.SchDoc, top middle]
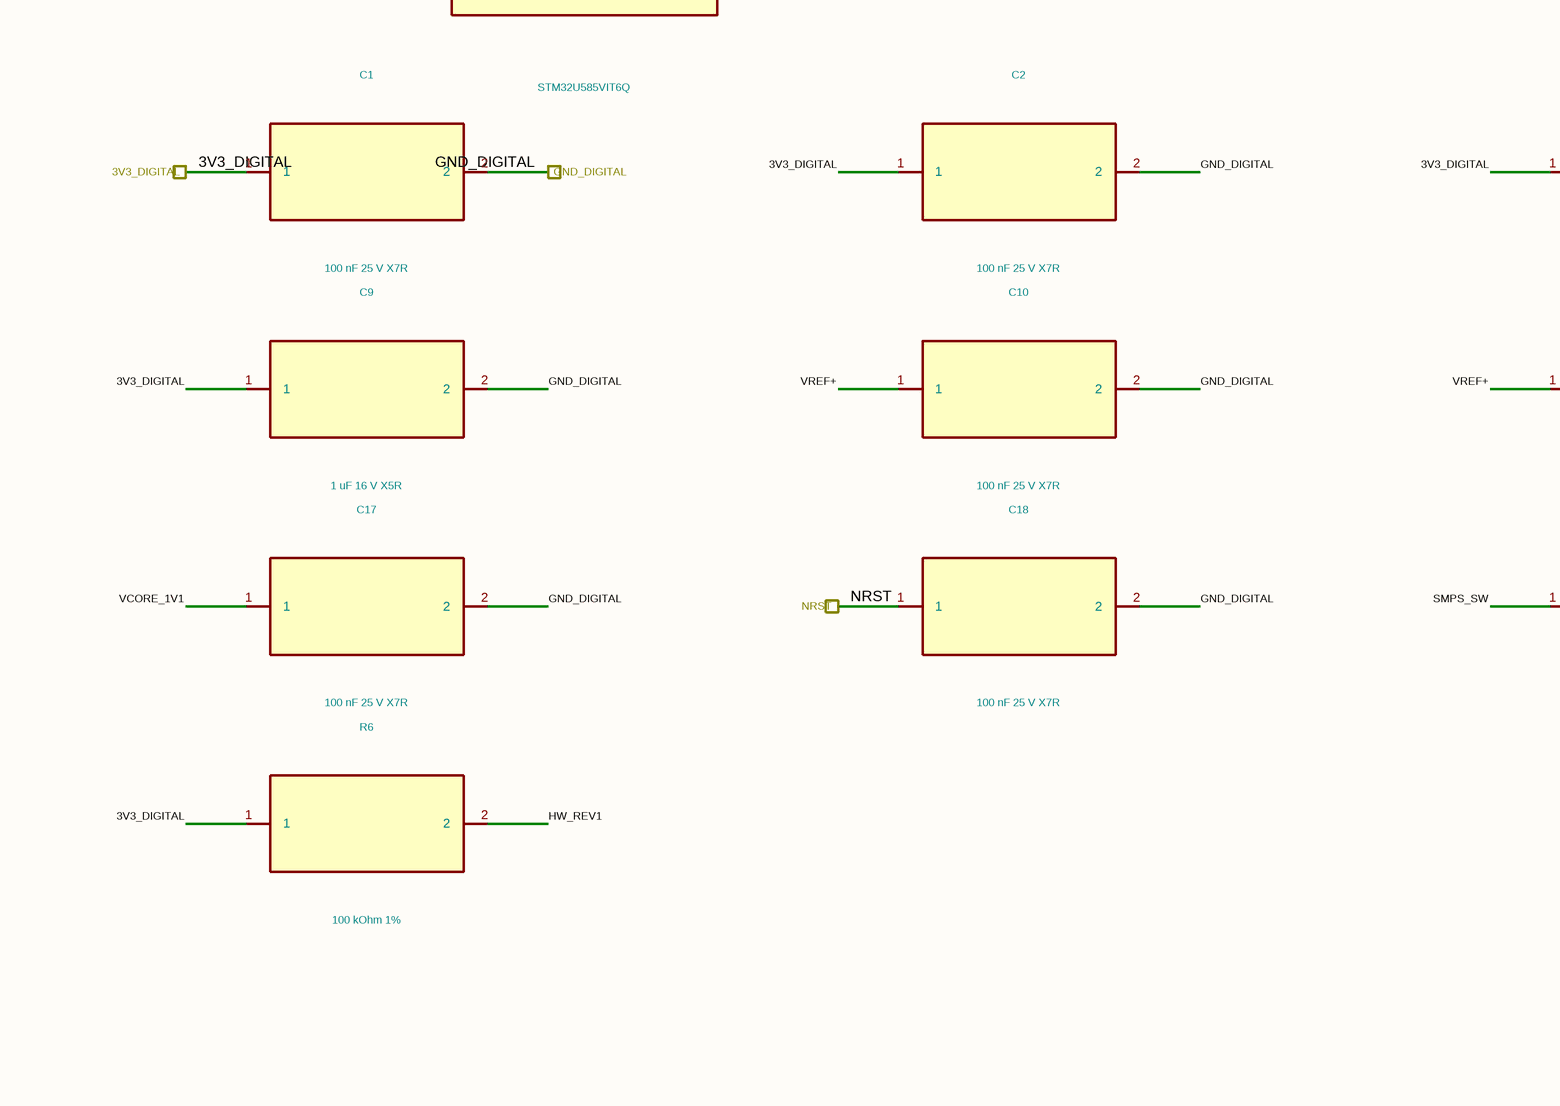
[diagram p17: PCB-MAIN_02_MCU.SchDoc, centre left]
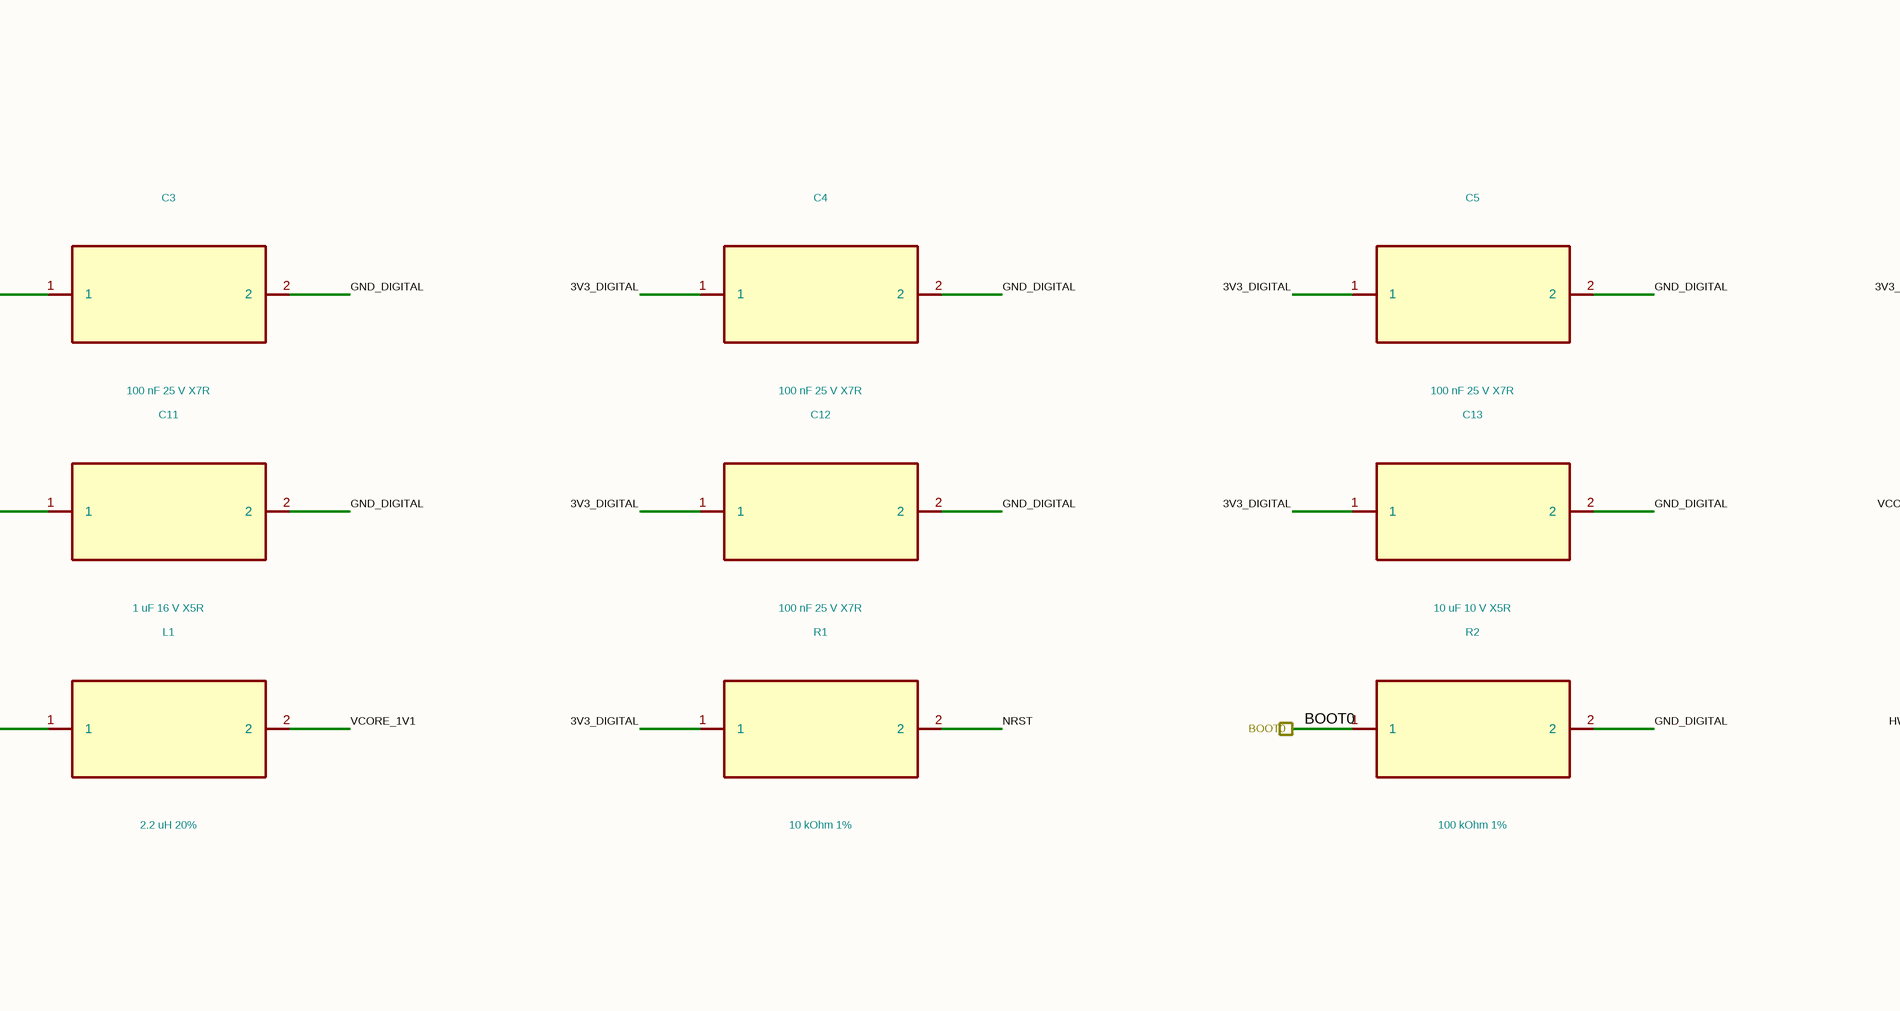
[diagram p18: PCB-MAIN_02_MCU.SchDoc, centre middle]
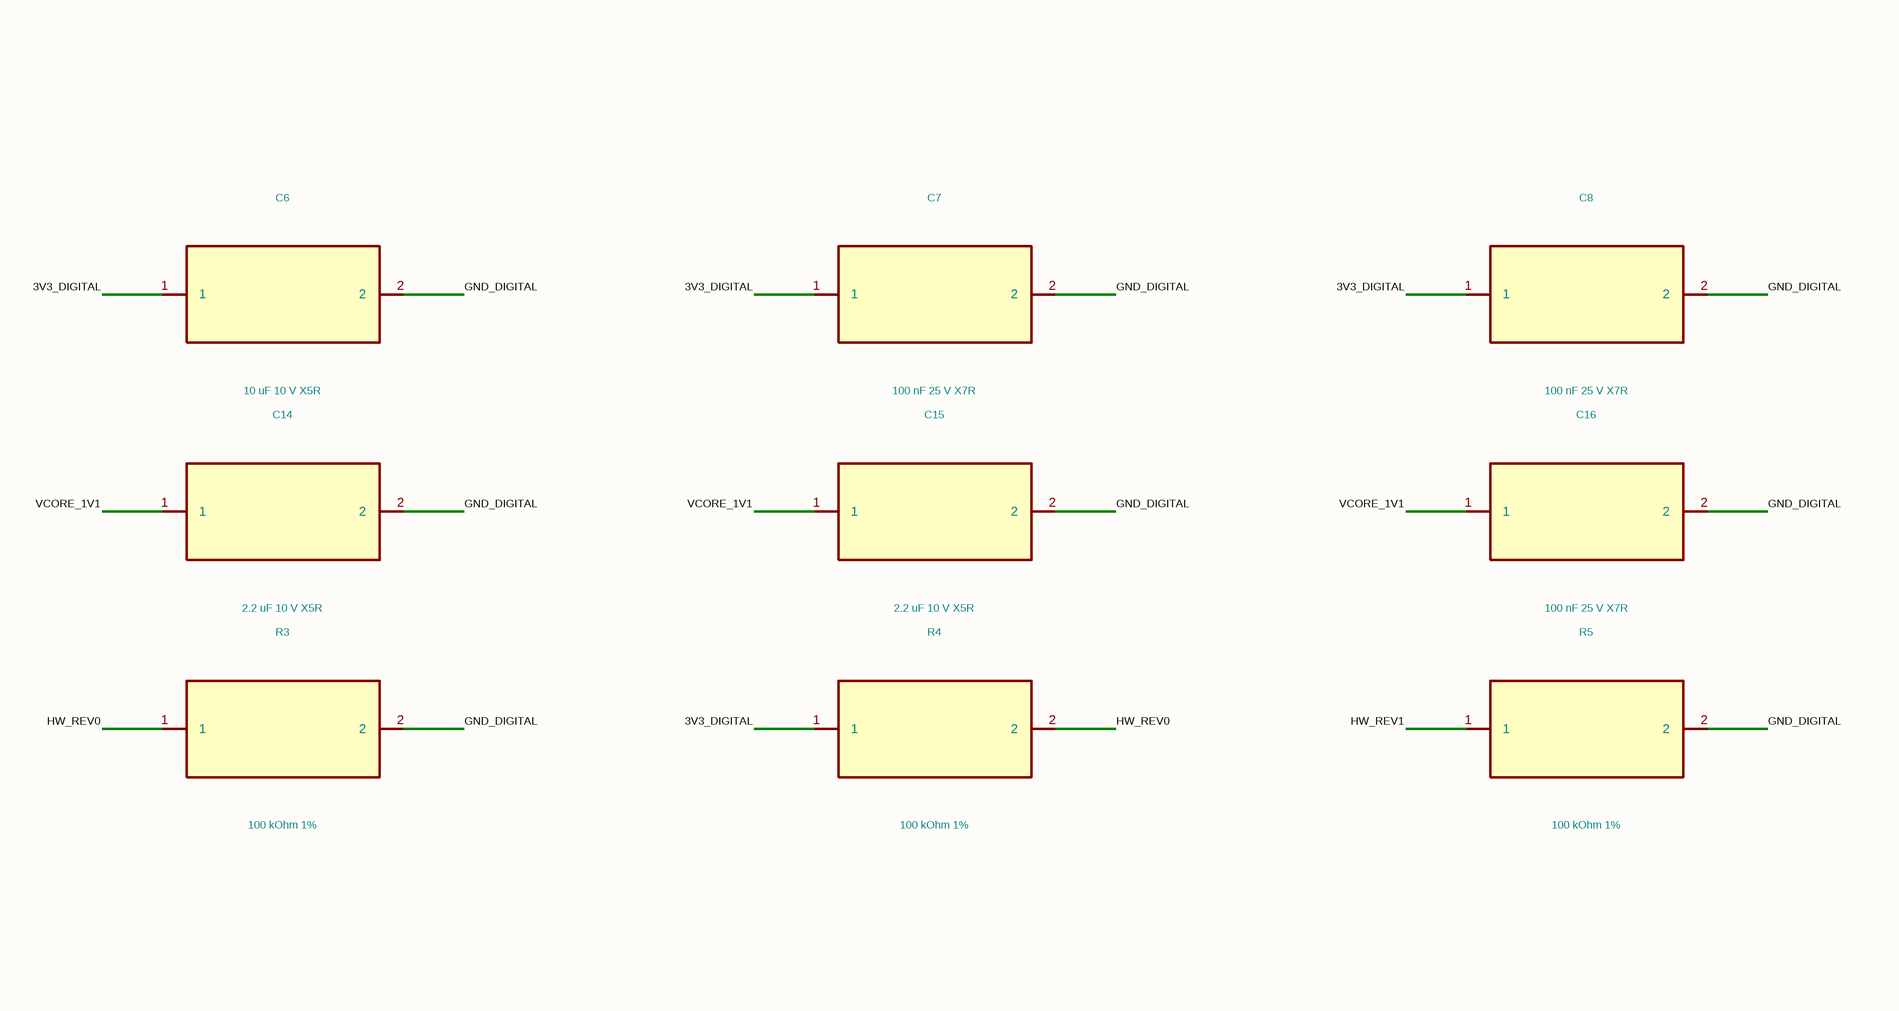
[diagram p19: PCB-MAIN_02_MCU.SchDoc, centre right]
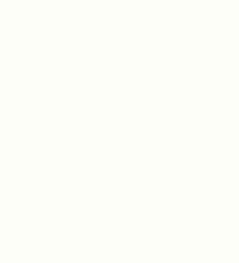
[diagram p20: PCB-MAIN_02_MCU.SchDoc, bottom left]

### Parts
C1  100 nF 25 V X7R  [C_0402_1005Metric]
C2  100 nF 25 V X7R  [C_0402_1005Metric]
C3  100 nF 25 V X7R  [C_0402_1005Metric]
C4  100 nF 25 V X7R  [C_0402_1005Metric]
C5  100 nF 25 V X7R  [C_0402_1005Metric]
C6  10 uF 10 V X5R  [C_0603_1608Metric]
C7  100 nF 25 V X7R  [C_0402_1005Metric]
C8  100 nF 25 V X7R  [C_0402_1005Metric]
C9  1 uF 16 V X5R  [C_0402_1005Metric]
C10  100 nF 25 V X7R  [C_0402_1005Metric]
C11  1 uF 16 V X5R  [C_0402_1005Metric]
C12  100 nF 25 V X7R  [C_0402_1005Metric]
C13  10 uF 10 V X5R  [C_0603_1608Metric]
C14  2.2 uF 10 V X5R  [C_0402_1005Metric]
C15  2.2 uF 10 V X5R  [C_0402_1005Metric]
C16  100 nF 25 V X7R  [C_0402_1005Metric]
C17  100 nF 25 V X7R  [C_0402_1005Metric]
C18  100 nF 25 V X7R  [C_0402_1005Metric]
L1  2.2 uH 20%  [L_1210_3225Metric]
R1  10 kOhm 1%  [R_0402_1005Metric]
R2  100 kOhm 1%  [R_0402_1005Metric]
R3  100 kOhm 1%  [R_0402_1005Metric]
R4  100 kOhm 1%  [R_0402_1005Metric]
R5  100 kOhm 1%  [R_0402_1005Metric]
R6  100 kOhm 1%  [R_0402_1005Metric]
U1  STM32U585VIT6Q
X1  32.768 kHz full-swing LVCMOS

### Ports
3V3_DIGITAL, AAD_CFG, ACCEL_INT, BLE_DFU_REQ, BLE_EN, BLE_RX_U1, BLE_TX_U1, BOOT0, CELL_DTR_U16, CELL_PWRKEY_CMD, CELL_RESET_N_CMD, CELL_RI_U16, CELL_RX_U16, CELL_STATUS_U16, CELL_TX_U16, EN_AUX, EN_MODEM, GND_DIGITAL, GNSS_PPS_U1, GNSS_RX_U1, GNSS_TX_U1, I2C2_SCL_U1, I2C2_SDA_U1, LORA_BUSY, LORA_DIO1, LORA_MISO_U1, LORA_MOSI_U1, LORA_NSS_U1, LORA_RESET_N, LORA_RXEN, LORA_SCK_U1, LORA_TXEN, MIC_WAKE, NOR_CLK_U1, NOR_IO0_U1, NOR_IO1_U1, NOR_IO2_U1, NOR_IO3_U1, NOR_NCS_U2, NRST, PDM_CLK, PDM_DATA1, PDM_DATA2, PDM_DATA3, PDM_DATA4, PWR_FAULT, PWR_GOOD, REV_STRAP0, REV_STRAP1, SD_CK_U1, SD_CMD_U1, SD_D0_U1, SD_D1_U1, SD_D2_U1, SD_D3_U1, SD_DET, SIM1_DET, SIM2_DET, SIM_MUX_EN, SIM_MUX_SEL, SWCLK, SWDIO, TAMPER_IN_U1, TEST_UART_RX_U1, TEST_UART_TX_U1, USB_DM_U1, USB_DP_U1, USB_VBUS_SENSE

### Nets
3V3_DIGITAL: C1.1 C2.1 C3.1 C4.1 C5.1 C6.1 C7.1 C8.1 C9.1 C12.1 C13.1 R1.1 R4.1 R6.1 U1.6(VBAT) U1.11(VDD) U1.20(VREF+) U1.21(VDDA) U1.27(VDD) U1.47(VDDSMPS) U1.51(VDD) U1.73(VDDUSB) U1.75(VDD) U1.100(VDD) X1.3 ; port 3V3_DIGITAL
AAD_CFG: U1.77(PA15_(JTDI)) ; port AAD_CFG
ACCEL_INT: U1.63(PC6) ; port ACCEL_INT
BLE_DFU_REQ: U1.34(PB2) ; port BLE_DFU_REQ
BLE_EN: U1.5(PE6) ; port BLE_EN
BLE_RX_U1: U1.45(PB11) ; port BLE_RX_U1
BLE_TX_U1: U1.44(PB10) ; port BLE_TX_U1
BOOT0: R2.1 U1.94(PH3-BOOT0) ; port BOOT0
CELL_DTR_U16: U1.61(PD14) ; port CELL_DTR_U16
CELL_PWRKEY_CMD: U1.58(PD11) ; port CELL_PWRKEY_CMD
CELL_RESET_N_CMD: U1.59(PD12) ; port CELL_RESET_N_CMD
CELL_RI_U16: U1.62(PD15) ; port CELL_RI_U16
CELL_RX_U16: U1.93(PB7) ; port CELL_RX_U16
CELL_STATUS_U16: U1.60(PD13) ; port CELL_STATUS_U16
CELL_TX_U16: U1.92(PB6) ; port CELL_TX_U16
EN_AUX: U1.86(PD5) ; port EN_AUX
EN_MODEM: U1.85(PD4) ; port EN_MODEM
GND_DIGITAL: C1.2 C2.2 C3.2 C4.2 C5.2 C6.2 C7.2 C8.2 C9.2 C10.2 C11.2 C12.2 C13.2 C14.2 C15.2 C16.2 C17.2 C18.2 R2.2 R3.2 R5.2 U1.10(VSS) U1.19(VSSA) U1.26(VSS) U1.48(VSSSMPS) U1.50(VSS) U1.74(VSS) U1.99(VSS) X1.1 X1.4 ; port GND_DIGITAL
GNSS_PPS_U1: U1.22(PA0) ; port GNSS_PPS_U1
GNSS_RX_U1: U1.25(PA3) ; port GNSS_RX_U1
GNSS_TX_U1: U1.24(PA2) ; port GNSS_TX_U1
HW_REV0: R3.1 R4.2
HW_REV1: R5.1 R6.2
I2C2_SCL_U1: U1.52(PB13) ; port I2C2_SCL_U1
I2C2_SDA_U1: U1.53(PB14) ; port I2C2_SDA_U1
LORA_BUSY: U1.56(PD9) ; port LORA_BUSY
LORA_DIO1: U1.17(PC2) ; port LORA_DIO1
LORA_MISO_U1: U1.30(PA6) ; port LORA_MISO_U1
LORA_MOSI_U1: U1.31(PA7) ; port LORA_MOSI_U1
LORA_NSS_U1: U1.28(PA4) ; port LORA_NSS_U1
LORA_RESET_N: U1.57(PD10) ; port LORA_RESET_N
LORA_RXEN: U1.55(PD8) ; port LORA_RXEN
LORA_SCK_U1: U1.29(PA5) ; port LORA_SCK_U1
LORA_TXEN: U1.54(PB15) ; port LORA_TXEN
LSE_IN: U1.8(PC14-OSC32_IN_(PC14)) X1.2
MIC_WAKE: U1.67(PA8) ; port MIC_WAKE
NOR_CLK_U1: U1.38(PE10) ; port NOR_CLK_U1
NOR_IO0_U1: U1.40(PE12) ; port NOR_IO0_U1
NOR_IO1_U1: U1.41(PE13) ; port NOR_IO1_U1
NOR_IO2_U1: U1.42(PE14) ; port NOR_IO2_U1
NOR_IO3_U1: U1.43(PE15) ; port NOR_IO3_U1
NOR_NCS_U2: U1.39(PE11) ; port NOR_NCS_U2
NRST: C18.1 R1.2 U1.14(NRST) ; port NRST
PDM_CLK: U1.37(PE9) ; port PDM_CLK
PDM_DATA1: U1.33(PB1) ; port PDM_DATA1
PDM_DATA2: U1.87(PD6) ; port PDM_DATA2
PDM_DATA3: U1.35(PE7) ; port PDM_DATA3
PDM_DATA4: U1.3(PE4) ; port PDM_DATA4
PWR_FAULT: U1.82(PD1) ; port PWR_FAULT
PWR_GOOD: U1.81(PD0) ; port PWR_GOOD
REV_STRAP0: U1.95(PB8) ; port REV_STRAP0
REV_STRAP1: U1.96(PB9) ; port REV_STRAP1
SD_CK_U1: U1.80(PC12) ; port SD_CK_U1
SD_CMD_U1: U1.83(PD2) ; port SD_CMD_U1
SD_D0_U1: U1.65(PC8) ; port SD_D0_U1
SD_D1_U1: U1.66(PC9) ; port SD_D1_U1
SD_D2_U1: U1.78(PC10) ; port SD_D2_U1
SD_D3_U1: U1.79(PC11) ; port SD_D3_U1
SD_DET: U1.7(PC13) ; port SD_DET
SIM1_DET: U1.2(PE3) ; port SIM1_DET
SIM2_DET: U1.4(PE5) ; port SIM2_DET
SIM_MUX_EN: U1.1(PE2) ; port SIM_MUX_EN
SIM_MUX_SEL: U1.97(PE0) ; port SIM_MUX_SEL
SMPS_SW: L1.1 U1.46(VLXSMPS)
SWCLK: U1.76(PA14_(JTCK/SWCLK)) ; port SWCLK
SWDIO: U1.72(PA13_(JTMS/SWDIO)) ; port SWDIO
TAMPER_IN_U1: U1.64(PC7) ; port TAMPER_IN_U1
TEST_UART_RX_U1: U1.15(PC0) ; port TEST_UART_RX_U1
TEST_UART_TX_U1: U1.16(PC1) ; port TEST_UART_TX_U1
USB_DM_U1: U1.70(PA11) ; port USB_DM_U1
USB_DP_U1: U1.71(PA12) ; port USB_DP_U1
USB_VBUS_SENSE: U1.68(PA9) ; port USB_VBUS_SENSE
VCORE_1V1: C14.1 C15.1 C16.1 C17.1 L1.2 U1.49(VDD11) U1.98(VDD11)
VREF+: C10.1 C11.1

Not connected (* = marked no-connect by the designer): U1 9(PC15-OSC32_OUT_(PC15))* 12(PH0-OSC_IN_(PH0))* 13(PH1-OSC_OUT_(PH1))* 18(PC3)* 23(PA1)* 32(PB0)* 36(PE8)* 69(PA10)* 84(PD3)* 88(PD7)* 89(PB3_(JTDO/TRACESWO))* 90(PB4_(NJTRST))* 91(PB5)*

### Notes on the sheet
- Every connected symbol pin has one explicit wire stub. Only hierarchical labels cross functional-sheet boundaries.

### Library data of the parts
C1 = C1_GRM155R71E104KE14D: Manufacturer: Murata; Population: FITTED; Authority: ST_AN5373_Rev7
C2 = C2_GRM155R71E104KE14D: Manufacturer: Murata; Population: FITTED; Authority: ST_AN5373_Rev7
C3 = C3_GRM155R71E104KE14D: Manufacturer: Murata; Population: FITTED; Authority: ST_AN5373_Rev7
C4 = C4_GRM155R71E104KE14D: Manufacturer: Murata; Population: FITTED; Authority: ST_AN5373_Rev7
C5 = C5_GRM155R71E104KE14D: Manufacturer: Murata; Population: FITTED; Authority: ST_AN5373_Rev7
C6 = C6_GRM188R61A106KE69D: Manufacturer: Murata; Population: FITTED; Authority: ST_AN5373_Rev7
C7 = C7_GRM155R71E104KE14D: Manufacturer: Murata; Population: FITTED; Authority: ST_AN5373_Rev7
C8 = C8_GRM155R71E104KE14D: Manufacturer: Murata; Population: FITTED; Authority: ST_AN5373_Rev7
C9 = C9_GRM155R61C105KA12D: Manufacturer: Murata; Population: FITTED; Authority: ST_AN5373_Rev7
C10 = C10_GRM155R71E104KE14D: Manufacturer: Murata; Population: FITTED; Authority: ST_AN5373_Rev7
C11 = C11_GRM155R61C105KA12D: Manufacturer: Murata; Population: FITTED; Authority: ST_AN5373_Rev7
C12 = C12_GRM155R71E104KE14D: Manufacturer: Murata; Population: FITTED; Authority: ST_AN5373_Rev7
C13 = C13_GRM188R61A106KE69D: Manufacturer: Murata; Population: FITTED; Authority: ST_AN5373_Rev7
C14 = C14_GRM155R61A225KE15D: Manufacturer: Murata; Population: FITTED; Authority: ST_AN5373_Rev7
C15 = C15_GRM155R61A225KE15D: Manufacturer: Murata; Population: FITTED; Authority: ST_AN5373_Rev7
C16 = C16_GRM155R71E104KE14D: Manufacturer: Murata; Population: DNP; Authority: ST_AN5373_Rev7
C17 = C17_GRM155R71E104KE14D: Manufacturer: Murata; Population: DNP; Authority: ST_AN5373_Rev7
C18 = C18_GRM155R71E104KE14D: Manufacturer: Murata; Population: FITTED; Authority: ST_AN5373_Rev7
L1 = L1_LQH32PN2R2NN0L: Manufacturer: Murata; Population: FITTED; Authority: ST_AN5373_Rev7
R1 = R1_ERJ-2RKF1002X: Manufacturer: Panasonic; Population: FITTED; Authority: ST_AN5373_Rev7
R2 = R2_ERJ-2RKF1003X: Manufacturer: Panasonic; Population: FITTED; Authority: ST_AN2606
R3 = R3_ERJ-2RKF1003X: Manufacturer: Panasonic; Population: FITTED; Authority: PROJECT_MAIN_AUTH_010
R4 = R4_ERJ-2RKF1003X: Manufacturer: Panasonic; Population: DNP; Authority: PROJECT_MAIN_AUTH_010
R5 = R5_ERJ-2RKF1003X: Manufacturer: Panasonic; Population: FITTED; Authority: PROJECT_MAIN_AUTH_010
R6 = R6_ERJ-2RKF1003X: Manufacturer: Panasonic; Population: DNP; Authority: PROJECT_MAIN_AUTH_010
U1 = U1_STM32U585VIT6Q: Manufacturer: STMicroelectronics; Population: FITTED; Authority: PCB_MAIN_MCU_PIN_AUTHORITY_REV_A.csv
X1 = X1_SiT1552AI-JE-DCC-32.768D: Manufacturer: SiTime; Population: FITTED; Authority: SiTime_SiT1552_Rev1.43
